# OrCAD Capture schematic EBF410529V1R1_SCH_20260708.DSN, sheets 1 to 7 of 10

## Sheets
1 06 ETH0: size A4; title: 鲁班猫3金手指底板（LubanCat 3_IOF ） RK3576; rev: V0.1; note: ETH0; note: https://yehuosm.tmall.com
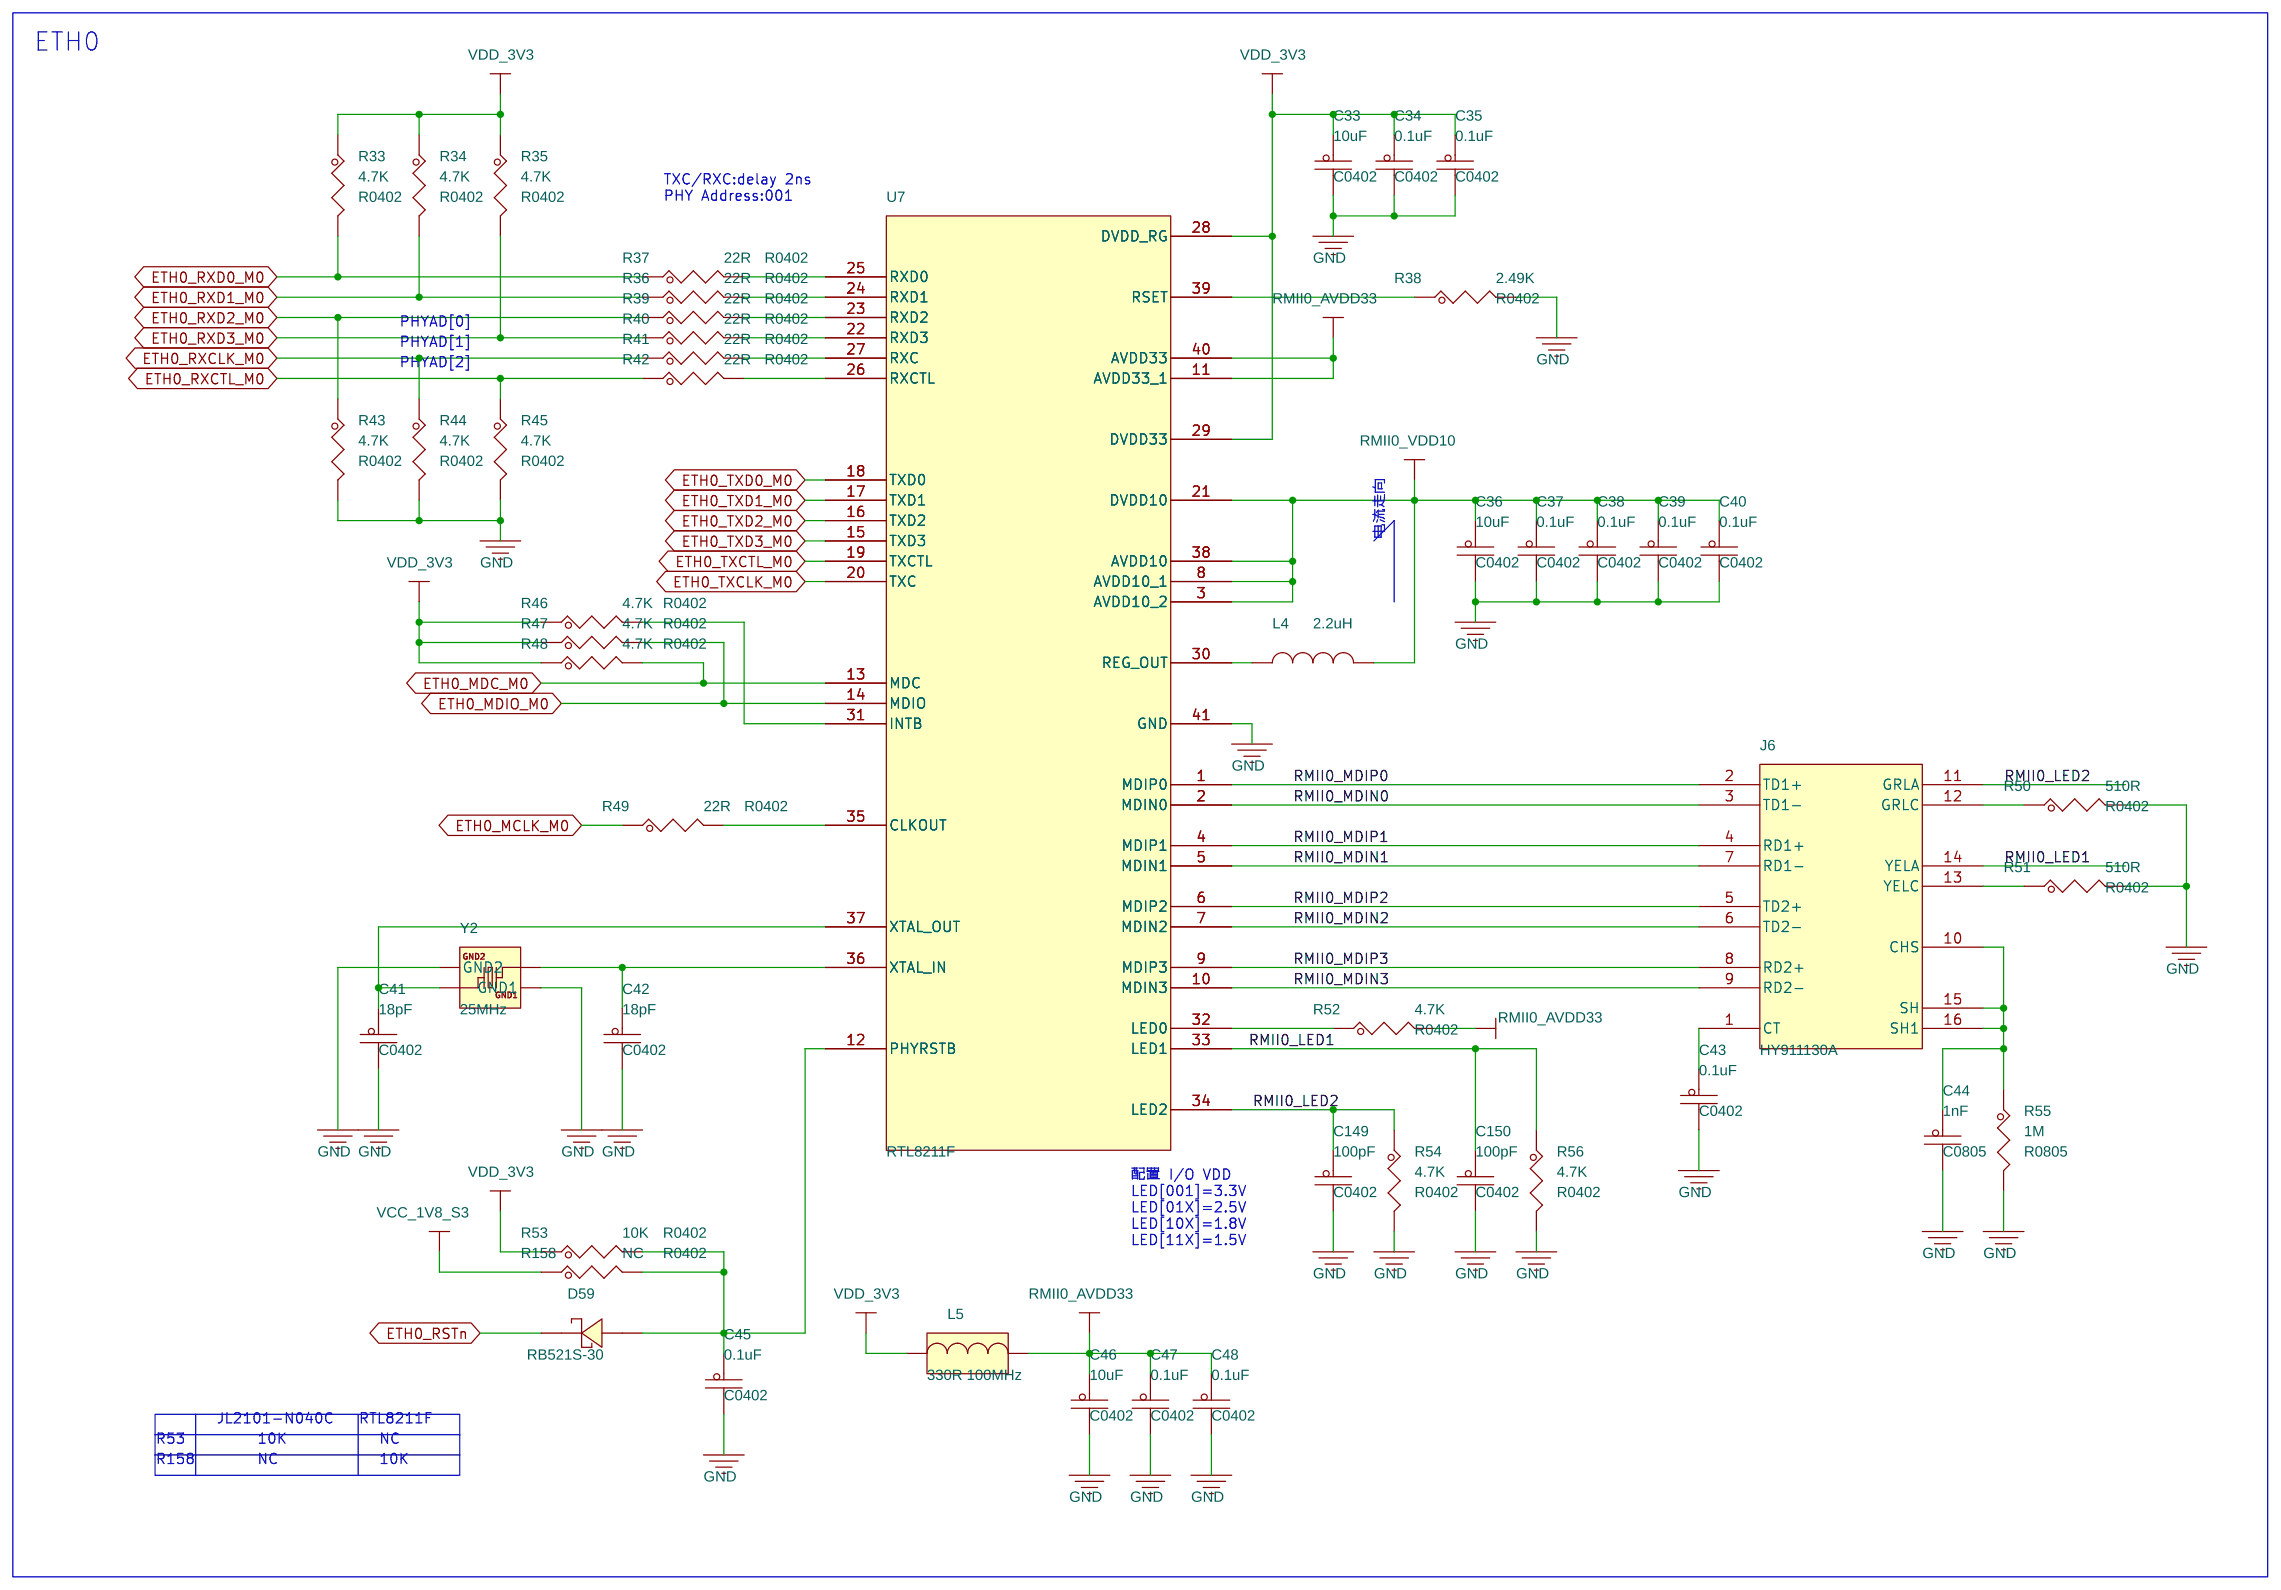
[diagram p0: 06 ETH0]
2 07 ETH1: size A4; note: ETH1
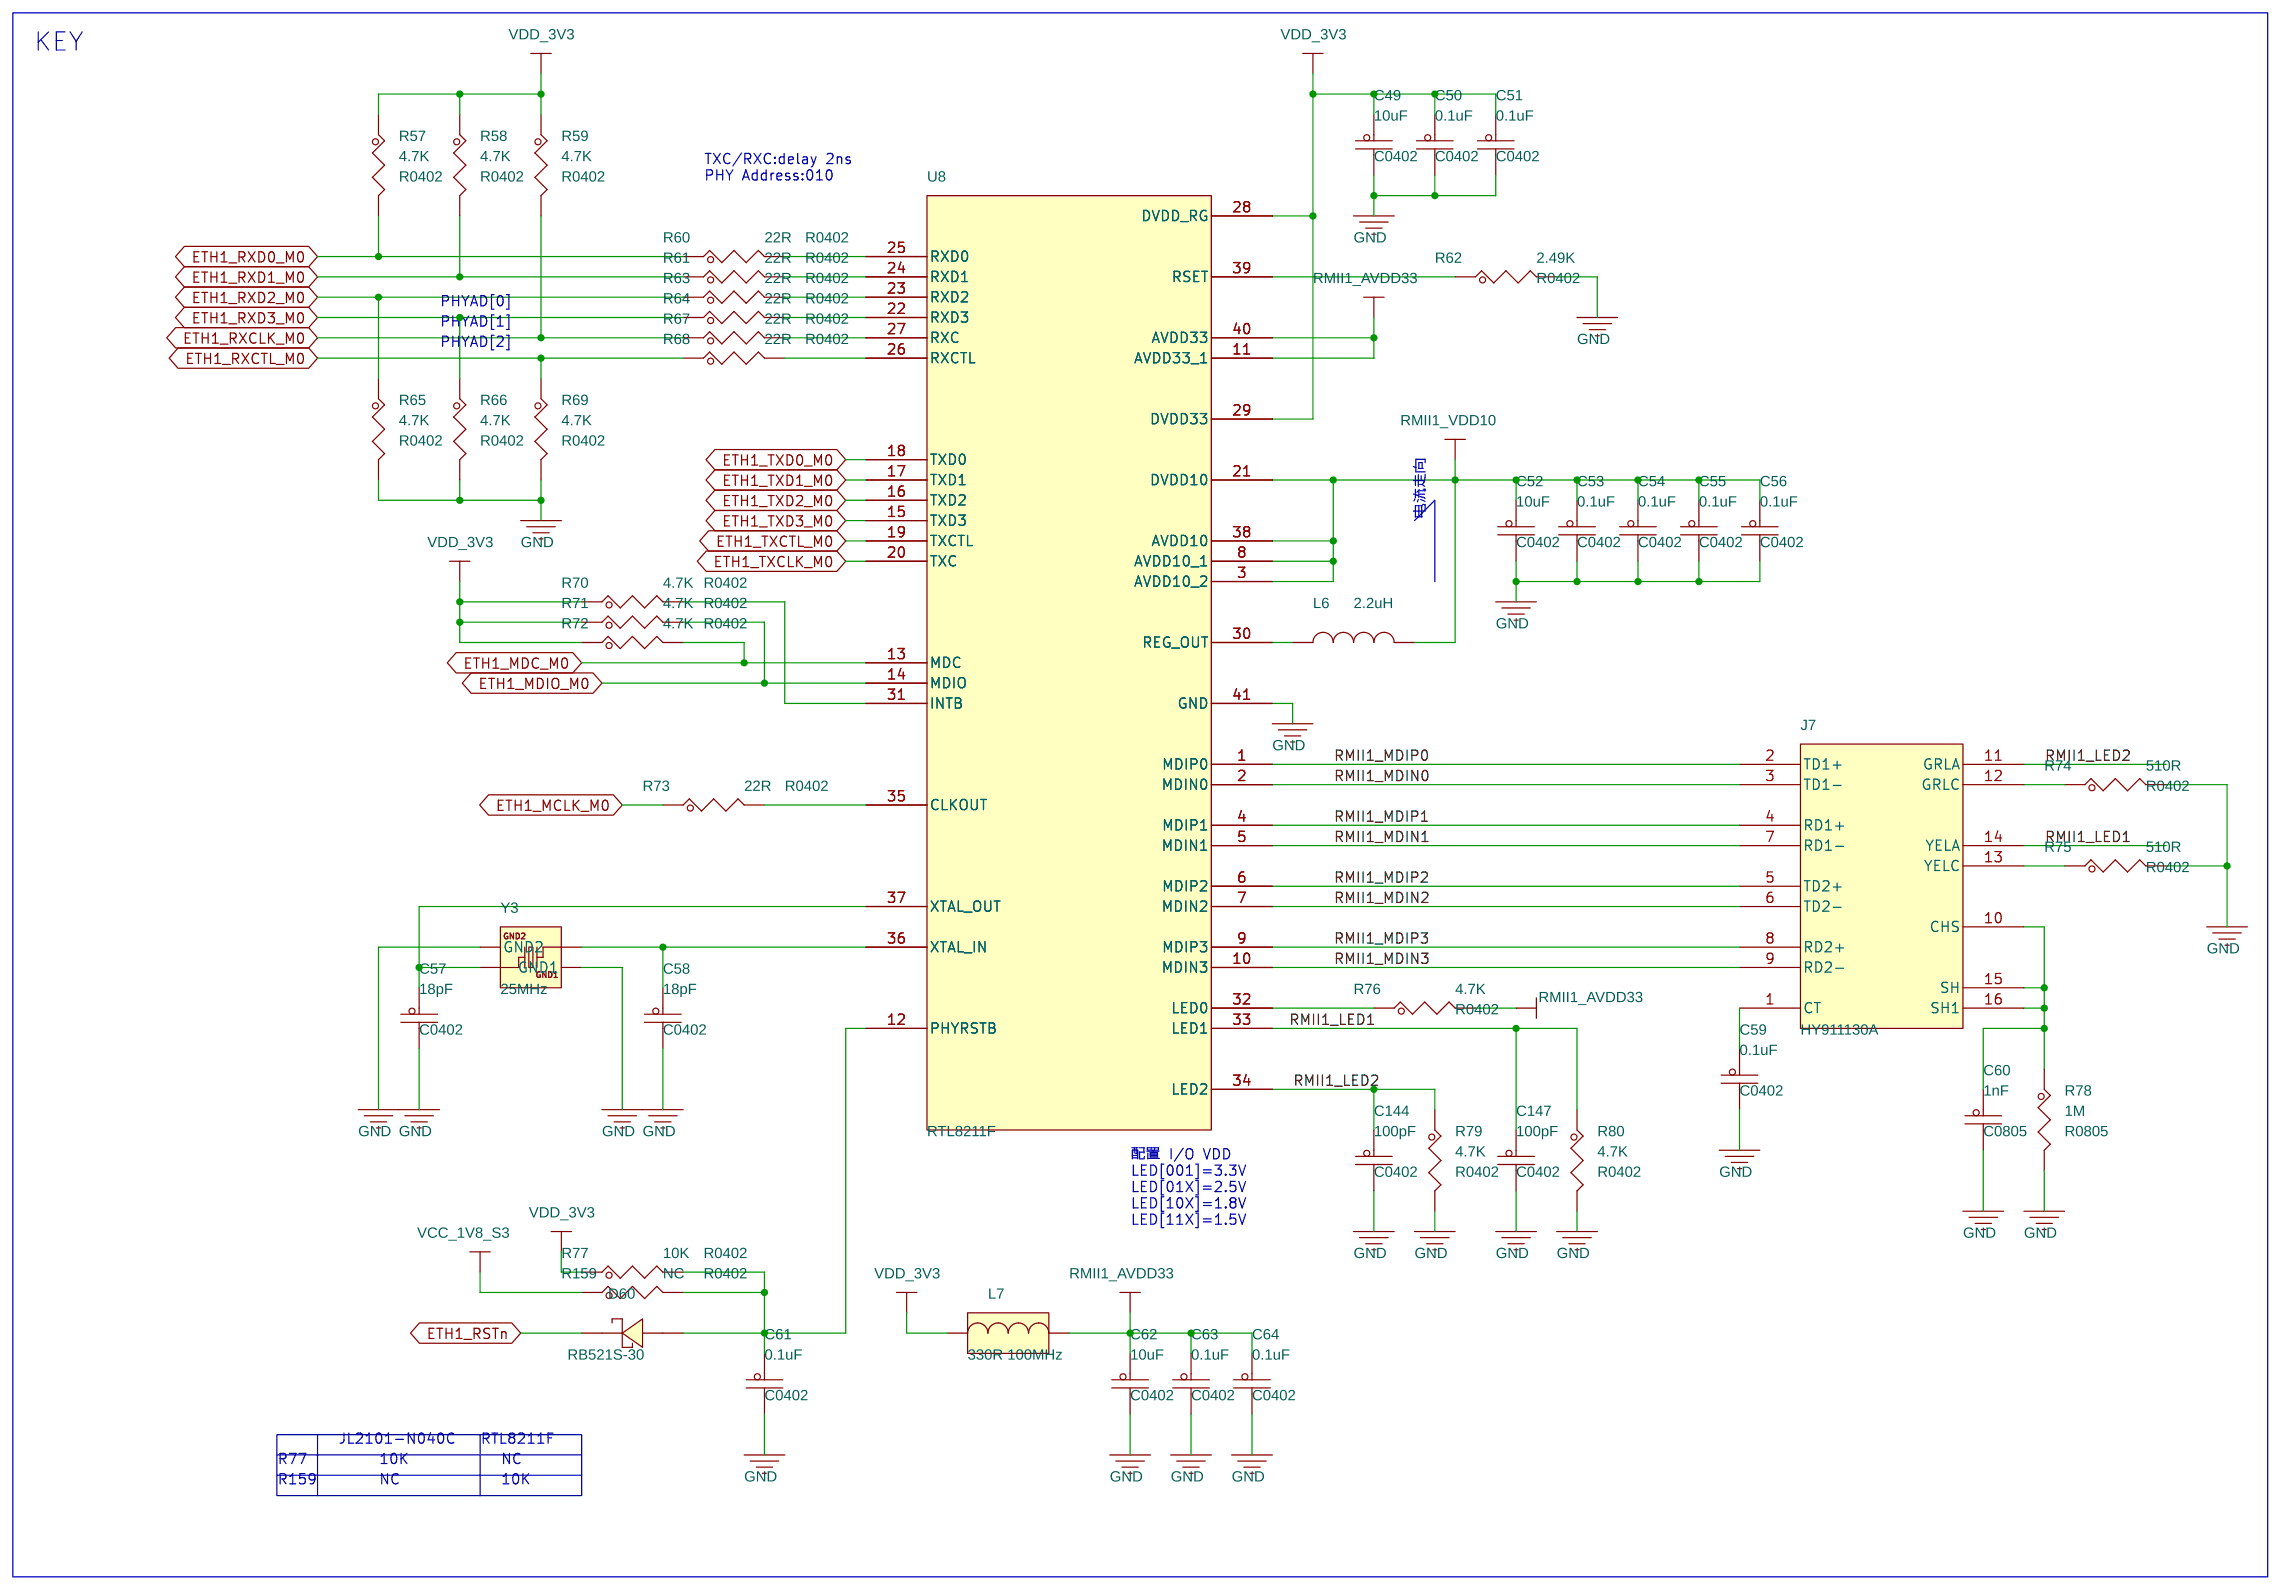
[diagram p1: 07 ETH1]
3 11 MIPI CSI PORT: size A4; note: MIPI CSI PORT
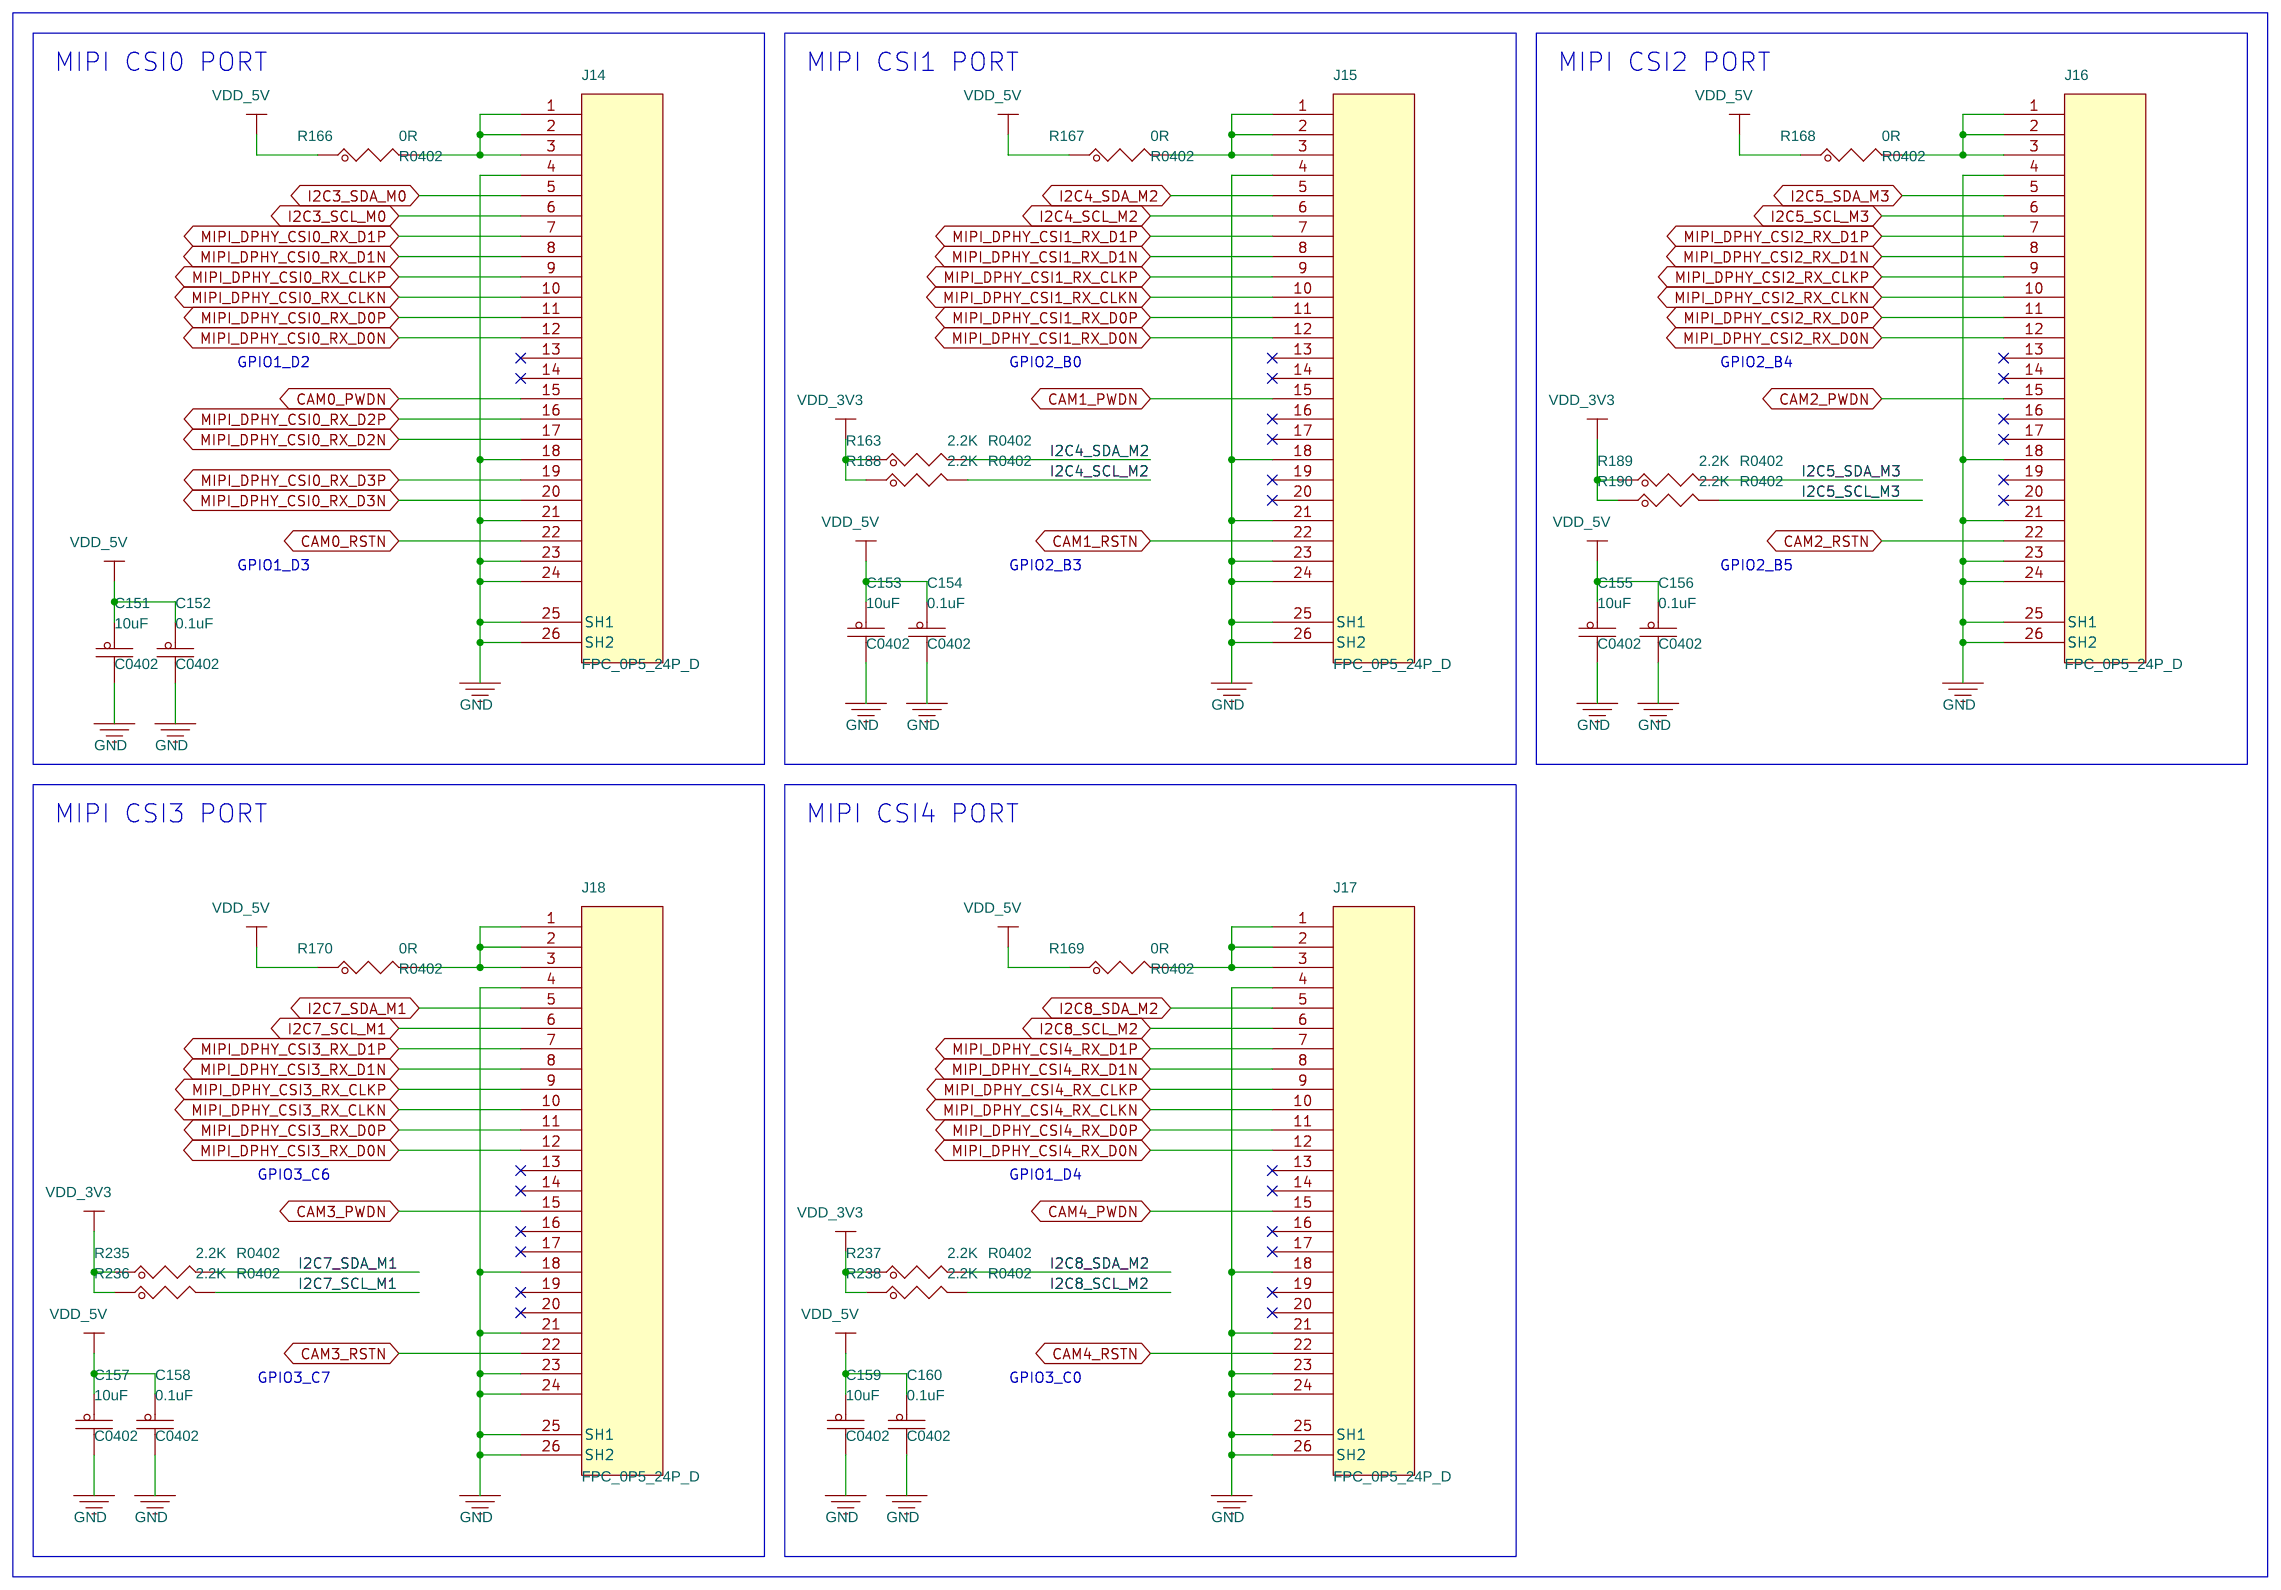
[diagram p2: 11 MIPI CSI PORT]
4 12 MINI PCIE PORT: size A4; note: MINI PCIE PORT
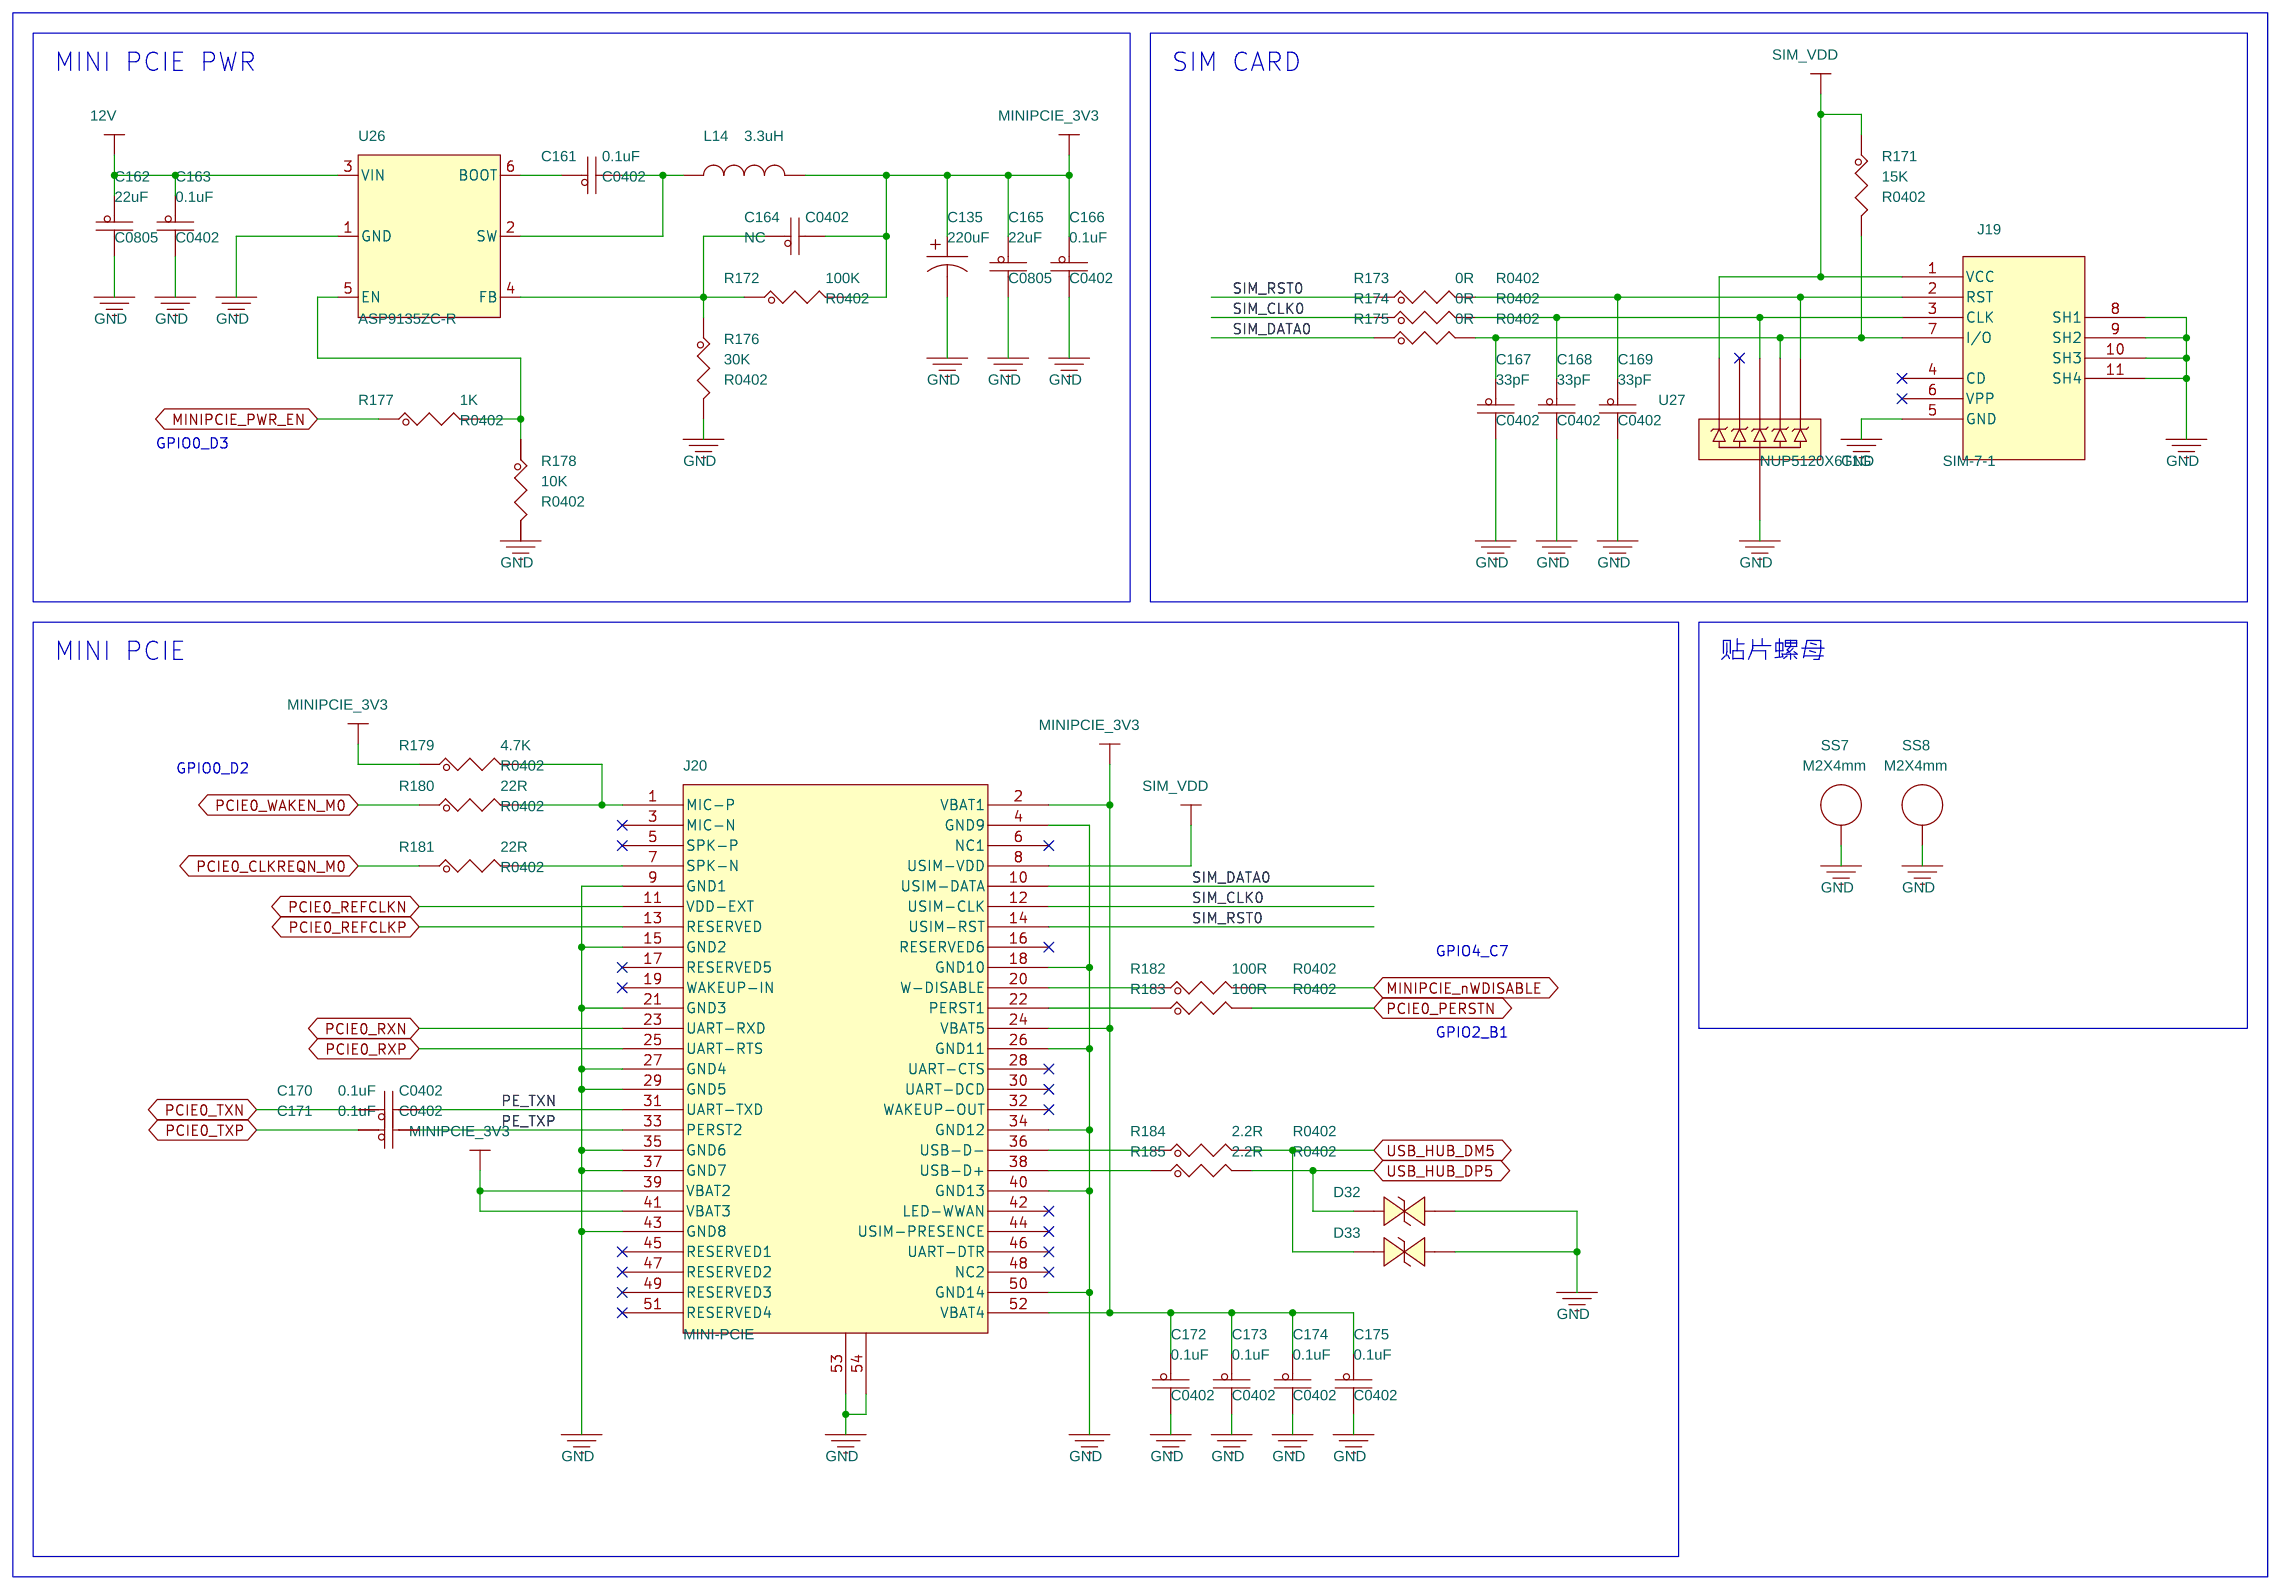
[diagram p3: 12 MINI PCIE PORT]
5 14 POWER OUT PORT: size A4; note: POWER OUT PORT
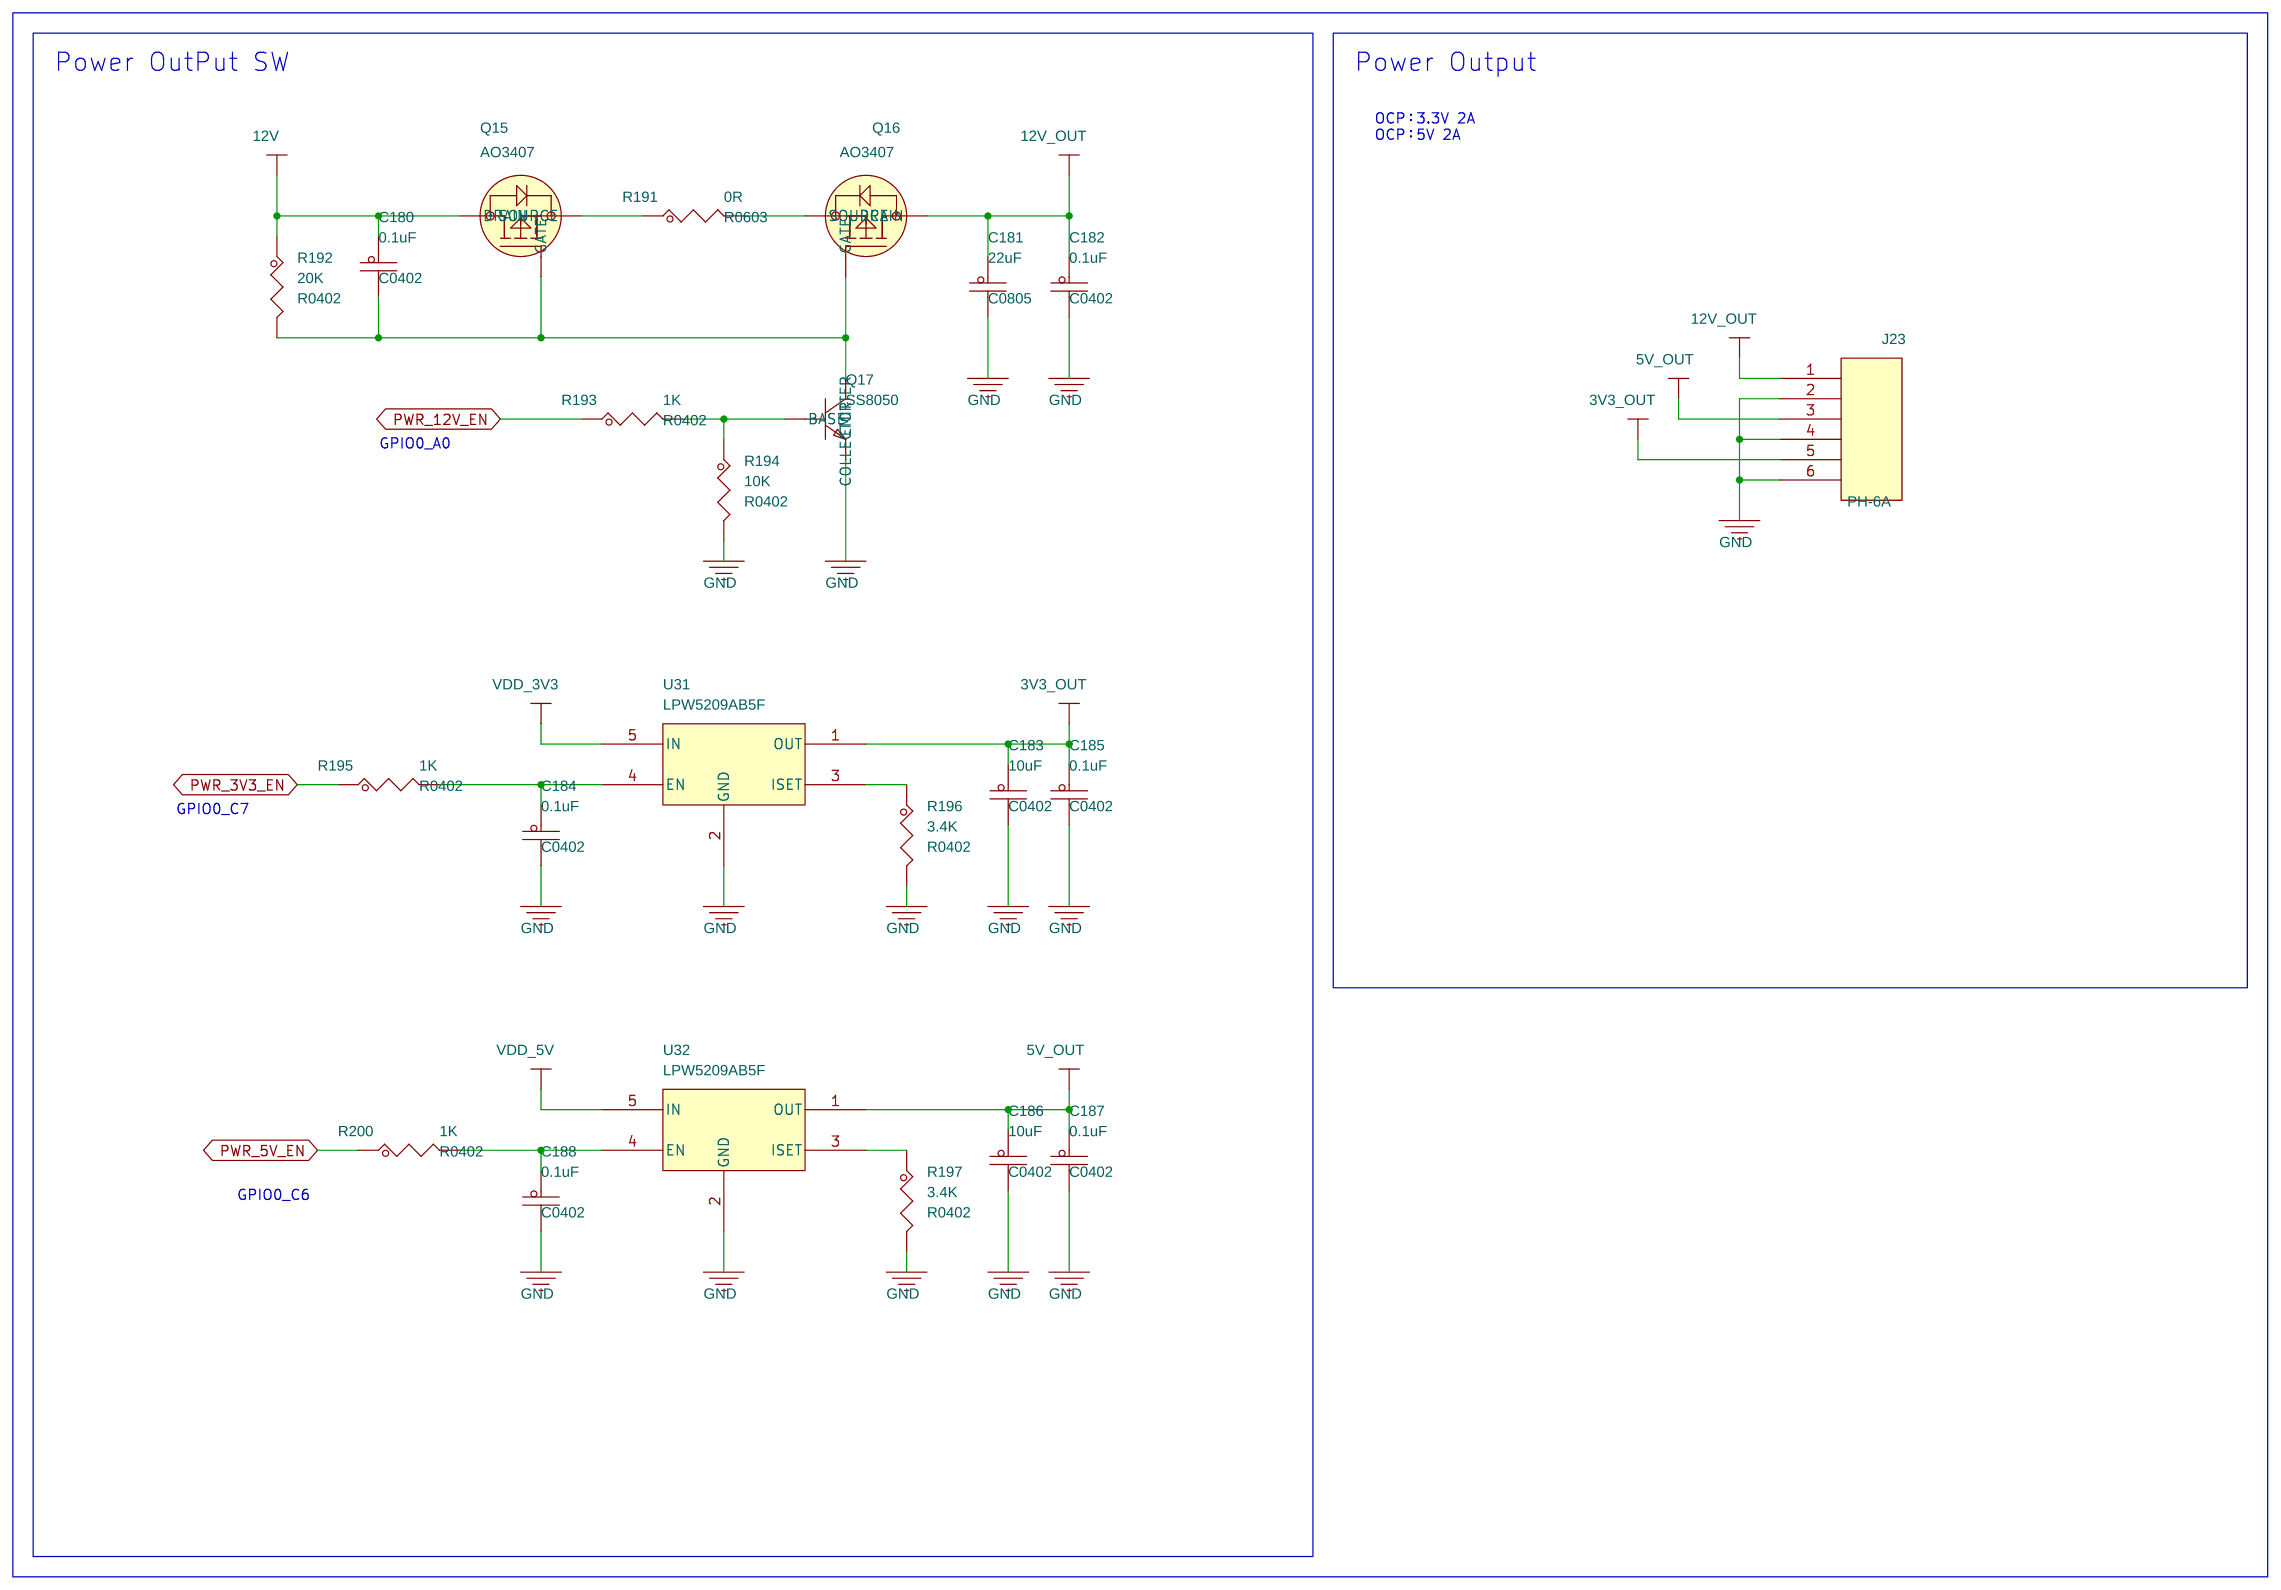
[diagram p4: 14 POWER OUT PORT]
6 08 Audio/WIFI: size A3; note: Audio/WIFI
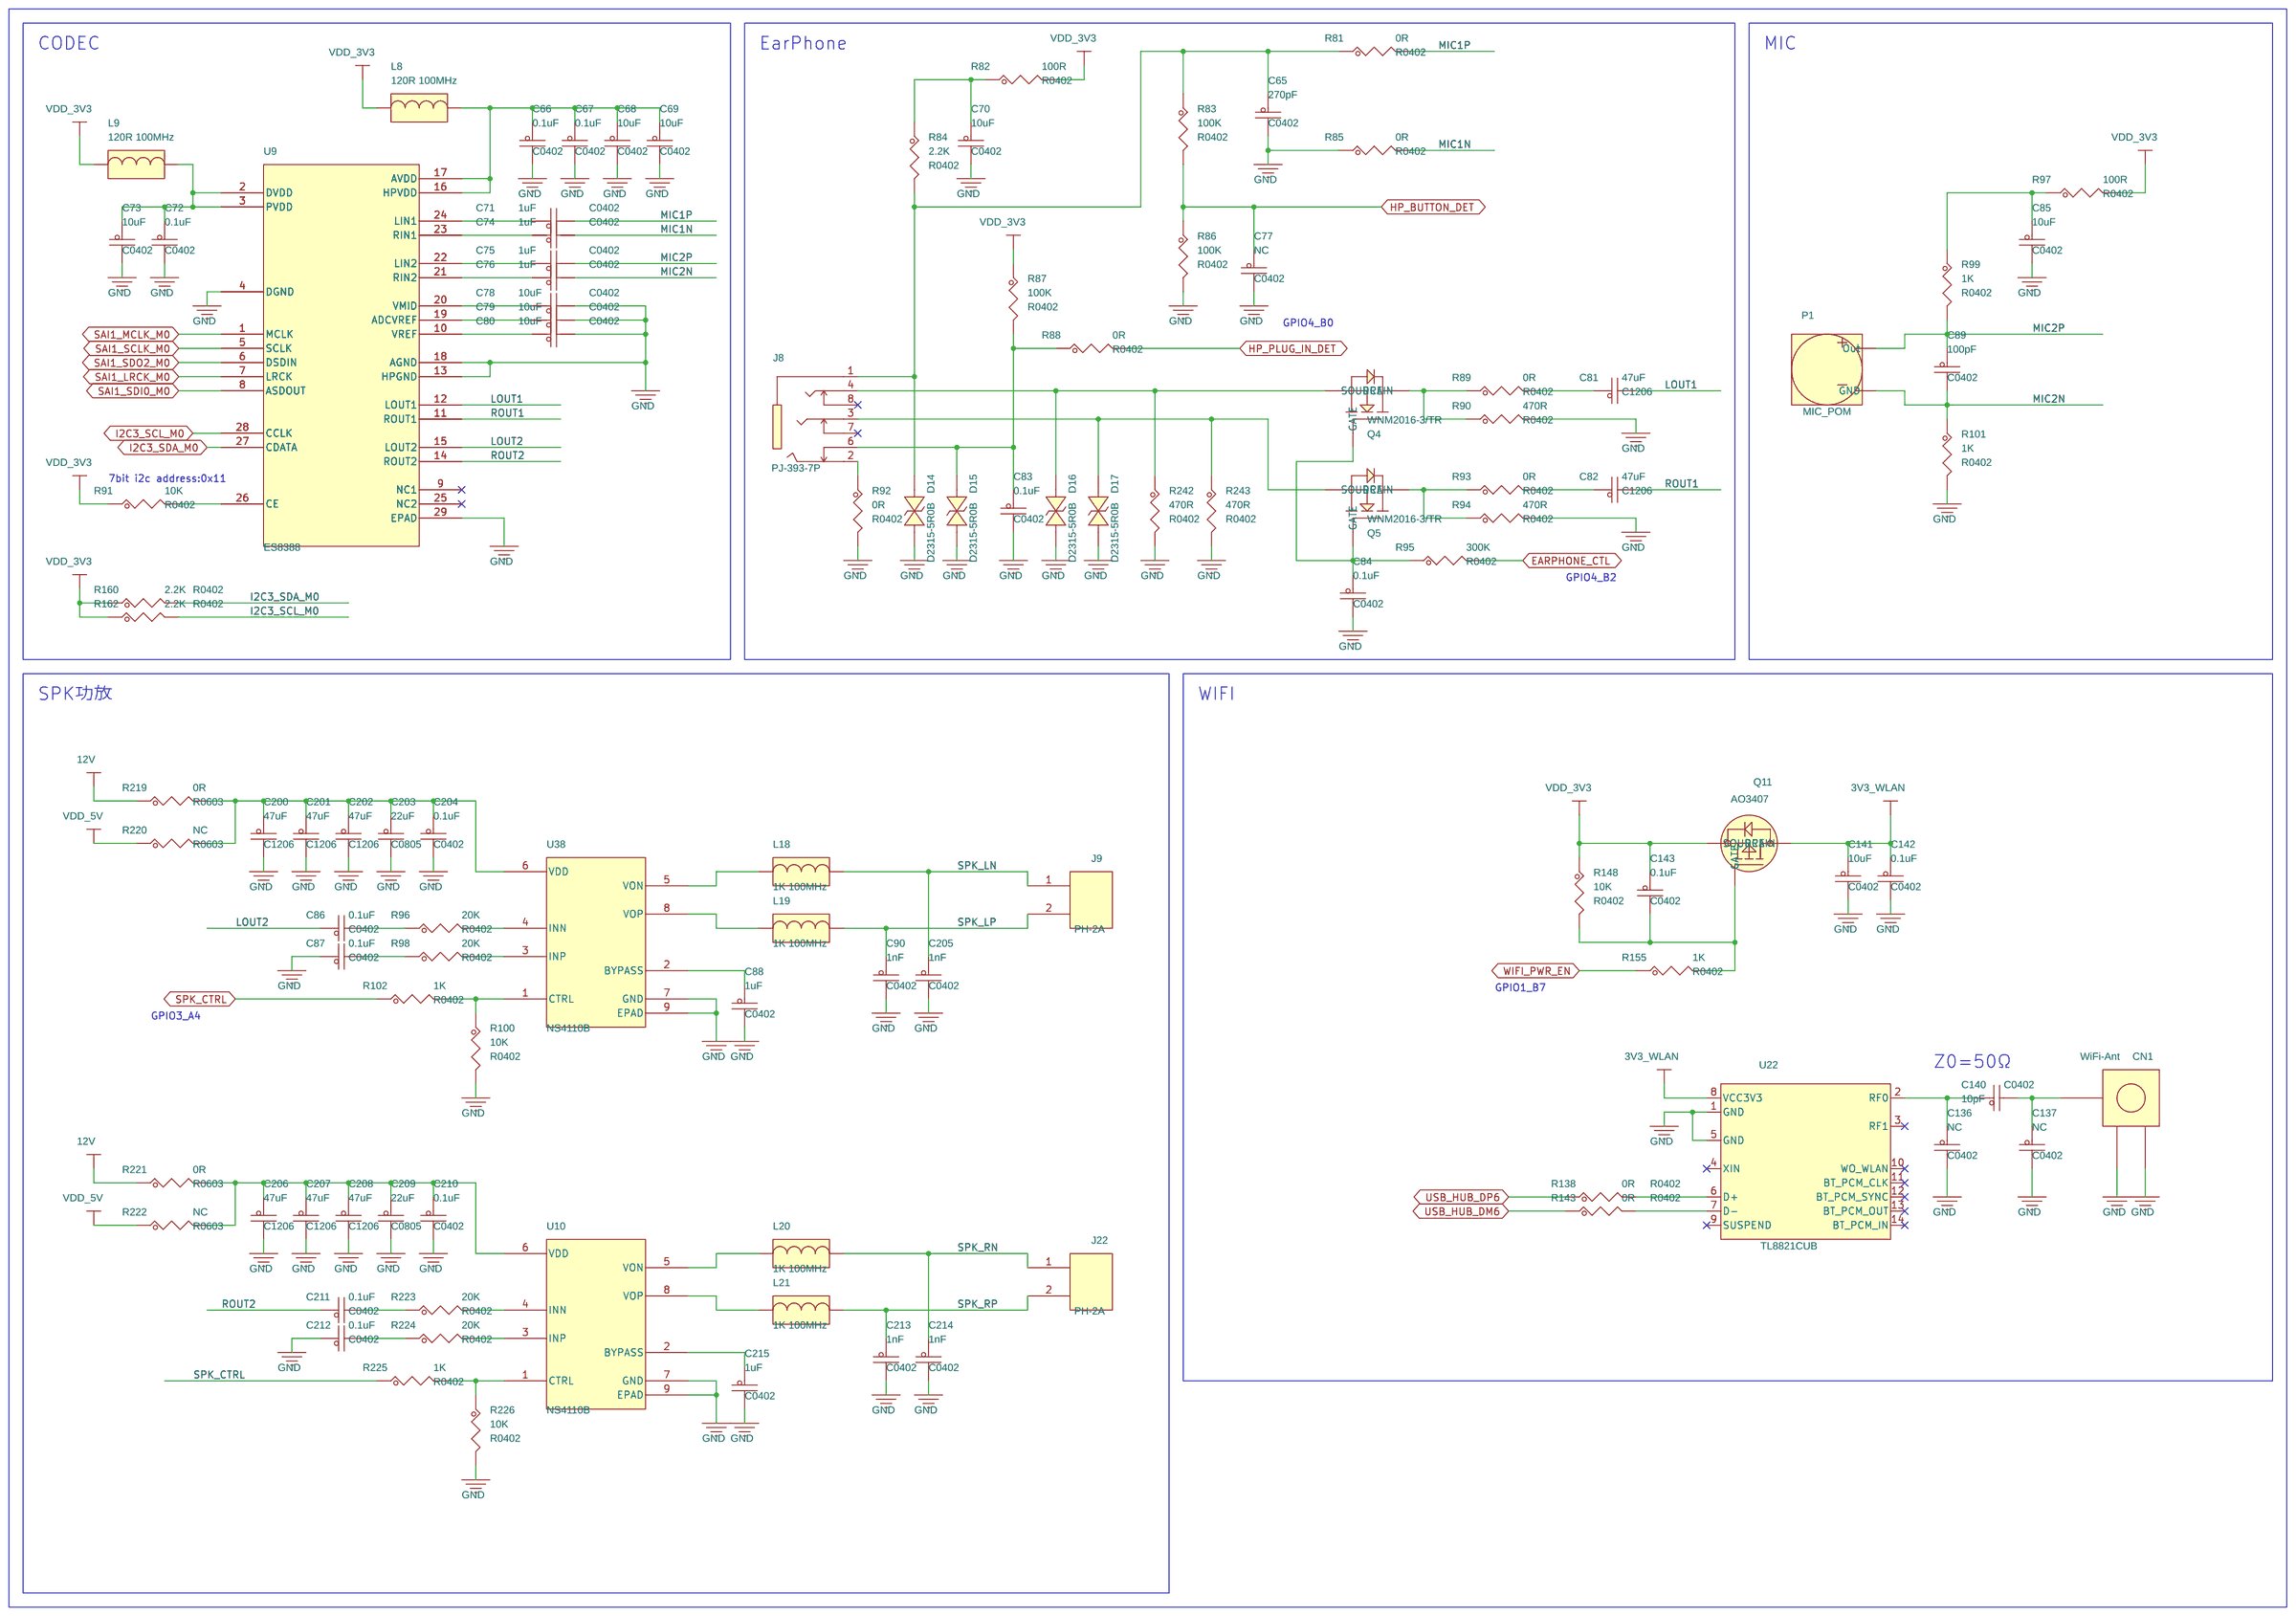
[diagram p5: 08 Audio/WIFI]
7 15 RS232/485/CAN: size A4; note: RS232/485/CAN
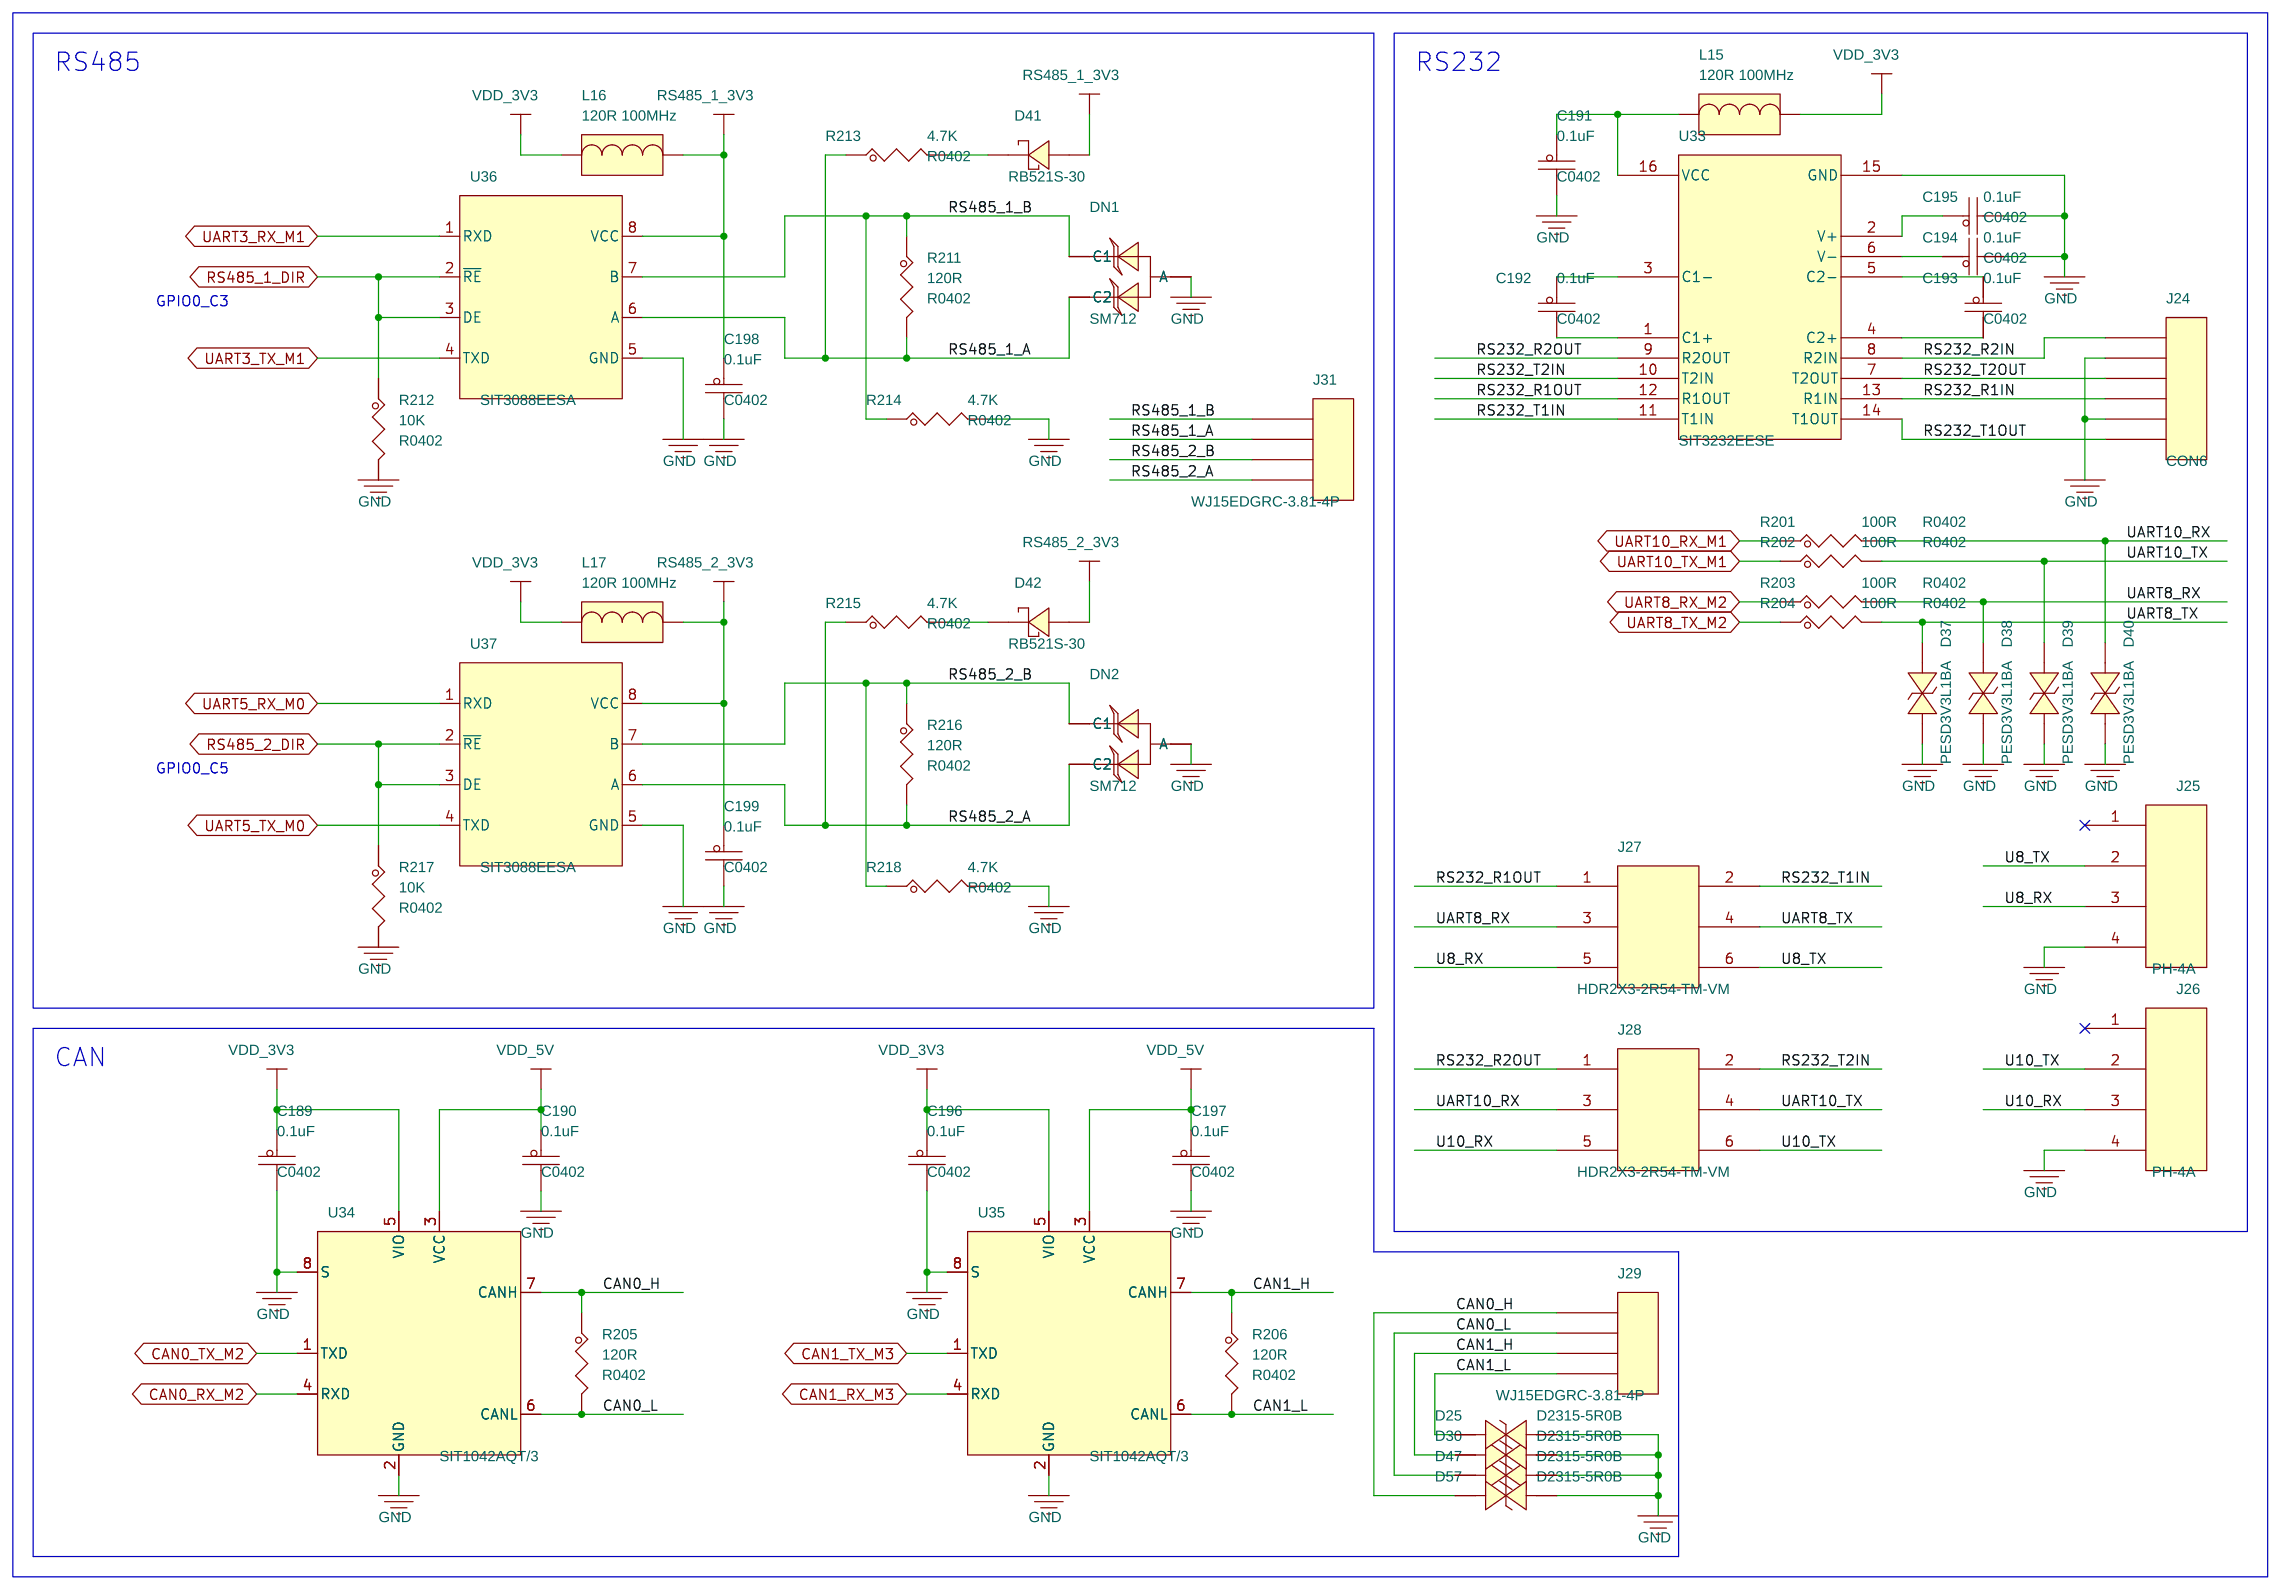
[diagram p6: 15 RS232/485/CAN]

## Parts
sheet 06 ETH0
C33  10uF  [C0402]
C34  0.1uF  [C0402]
C35  0.1uF  [C0402]
C36  10uF  [C0402]
C37  0.1uF  [C0402]
C38  0.1uF  [C0402]
C39  0.1uF  [C0402]
C40  0.1uF  [C0402]
C41  18pF  [C0402]
C42  18pF  [C0402]
C43  0.1uF  [C0402]
C44  1nF  [C0805]
C45  0.1uF  [C0402]
C46  10uF  [C0402]
C47  0.1uF  [C0402]
C48  0.1uF  [C0402]
C149  100pF  [C0402]
C150  100pF  [C0402]
D59  RB521S-30  [SOD523]
J6  HY911130A  [HY911130A]
L4  2.2uH  [L2520]
L5  330R 100MHz  [L0603]
R33  4.7K  [R0402]
R34  4.7K  [R0402]
R35  4.7K  [R0402]
R36  22R  [R0402]
R37  22R  [R0402]
R38  2.49K  [R0402]
R39  22R  [R0402]
R40  22R  [R0402]
R41  22R  [R0402]
R42  22R  [R0402]
R43  4.7K  [R0402]
R44  4.7K  [R0402]
R45  4.7K  [R0402]
R46  4.7K  [R0402]
R47  4.7K  [R0402]
R48  4.7K  [R0402]
R49  22R  [R0402]
R50  510R  [R0402]
R51  510R  [R0402]
R52  4.7K  [R0402]
R53  10K  [R0402]
R54  4.7K  [R0402]
R55  1M  [R0805]
R56  4.7K  [R0402]
R158  NC  [R0402]
U7  RTL8211F  [qfp_40p_r]
Y2  25MHz  [3225]
sheet 07 ETH1
C49  10uF  [C0402]
C50  0.1uF  [C0402]
C51  0.1uF  [C0402]
C52  10uF  [C0402]
C53  0.1uF  [C0402]
C54  0.1uF  [C0402]
C55  0.1uF  [C0402]
C56  0.1uF  [C0402]
C57  18pF  [C0402]
C58  18pF  [C0402]
C59  0.1uF  [C0402]
C60  1nF  [C0805]
C61  0.1uF  [C0402]
C62  10uF  [C0402]
C63  0.1uF  [C0402]
C64  0.1uF  [C0402]
C144  100pF  [C0402]
C147  100pF  [C0402]
D60  RB521S-30  [SOD523]
J7  HY911130A  [HY911130A]
L6  2.2uH  [L2520]
L7  330R 100MHz  [L0603]
R57  4.7K  [R0402]
R58  4.7K  [R0402]
R59  4.7K  [R0402]
R60  22R  [R0402]
R61  22R  [R0402]
R62  2.49K  [R0402]
R63  22R  [R0402]
R64  22R  [R0402]
R65  4.7K  [R0402]
R66  4.7K  [R0402]
R67  22R  [R0402]
R68  22R  [R0402]
R69  4.7K  [R0402]
R70  4.7K  [R0402]
R71  4.7K  [R0402]
R72  4.7K  [R0402]
R73  22R  [R0402]
R74  510R  [R0402]
R75  510R  [R0402]
R76  4.7K  [R0402]
R77  10K  [R0402]
R78  1M  [R0805]
R79  4.7K  [R0402]
R80  4.7K  [R0402]
R159  NC  [R0402]
U8  RTL8211F  [qfp_40p_r]
Y3  25MHz  [3225]
sheet 08 Audio/WIFI
C65  270pF  [C0402]
C66  0.1uF  [C0402]
C67  0.1uF  [C0402]
C68  10uF  [C0402]
C69  10uF  [C0402]
C70  10uF  [C0402]
C71  1uF  [C0402]
C72  0.1uF  [C0402]
C73  10uF  [C0402]
C74  1uF  [C0402]
C75  1uF  [C0402]
C76  1uF  [C0402]
C77  NC  [C0402]
C78  10uF  [C0402]
C79  10uF  [C0402]
C80  10uF  [C0402]
C81  47uF  [C1206]
C82  47uF  [C1206]
C83  0.1uF  [C0402]
C84  0.1uF  [C0402]
C85  10uF  [C0402]
C86  0.1uF  [C0402]
C87  0.1uF  [C0402]
C88  1uF  [C0402]
C89  100pF  [C0402]
C90  1nF  [C0402]
C136  NC  [C0402]
C137  NC  [C0402]
C140  10pF  [C0402]
C141  10uF  [C0402]
C142  0.1uF  [C0402]
C143  0.1uF  [C0402]
C200  47uF  [C1206]
C201  47uF  [C1206]
C202  47uF  [C1206]
C203  22uF  [C0805]
C204  0.1uF  [C0402]
C205  1nF  [C0402]
C206  47uF  [C1206]
C207  47uF  [C1206]
C208  47uF  [C1206]
C209  22uF  [C0805]
C210  0.1uF  [C0402]
C211  0.1uF  [C0402]
C212  0.1uF  [C0402]
C213  1nF  [C0402]
C214  1nF  [C0402]
C215  1uF  [C0402]
CN1  WiFi-Ant  [UFL-3]
D14  D2315-5R0B  [esd0402]
D15  D2315-5R0B  [esd0402]
D16  D2315-5R0B  [esd0402]
D17  D2315-5R0B  [esd0402]
J8  PJ-393-7P  [AV7_6x14r50_TM]
J9  PH-2A  [PH-1x2-2P0_l]
J22  PH-2A  [PH-1x2-2P0_l]
L8  120R 100MHz  [L0402]
L9  120R 100MHz  [L0402]
L18  1K 100MHz  [L0603]
L19  1K 100MHz  [L0603]
L20  1K 100MHz  [L0603]
L21  1K 100MHz  [L0603]
P1  MIC_POM  [MIC2-4R00-TM]
Q4  WNM2016-3/TR  [SOT23]
Q5  WNM2016-3/TR  [SOT23]
Q11  AO3407  [SOT23]
R81  0R  [R0402]
R82  100R  [R0402]
R83  100K  [R0402]
R84  2.2K  [R0402]
R85  0R  [R0402]
R86  100K  [R0402]
R87  100K  [R0402]
R88  0R  [R0402]
R89  0R  [R0402]
R90  470R  [R0402]
R91  10K  [R0402]
R92  0R  [R0402]
R93  0R  [R0402]
R94  470R  [R0402]
R95  300K  [R0402]
R96  20K  [R0402]
R97  100R  [R0402]
R98  20K  [R0402]
R99  1K  [R0402]
R100  10K  [R0402]
R101  1K  [R0402]
R102  1K  [R0402]
R138  0R  [R0402]
R143  0R  [R0402]
R148  10K  [R0402]
R155  1K  [R0402]
R160  2.2K  [R0402]
R162  2.2K  [R0402]
R219  0R  [R0603]
R220  NC  [R0603]
R221  0R  [R0603]
R222  NC  [R0603]
R223  20K  [R0402]
R224  20K  [R0402]
R225  1K  [R0402]
R226  10K  [R0402]
R242  470R  [R0402]
R243  470R  [R0402]
U9  ES8388  [qfn28_0r45-4x4EP2R6X2R6]
U10  NS4110B  [SOP-8-EP-2R5X3R4]
U22  TL8821CUB  [RL-UM02WBS-8723BU]
U38  NS4110B  [SOP-8-EP-2R5X3R4]
sheet 11 MIPI CSI PORT
C151  10uF  [C0402]
C152  0.1uF  [C0402]
C153  10uF  [C0402]
C154  0.1uF  [C0402]
C155  10uF  [C0402]
C156  0.1uF  [C0402]
C157  10uF  [C0402]
C158  0.1uF  [C0402]
C159  10uF  [C0402]
C160  0.1uF  [C0402]
J14  FPC_0P5_24P_D  [fpc_24p_0p5]
J15  FPC_0P5_24P_D  [fpc_24p_0p5]
J16  FPC_0P5_24P_D  [fpc_24p_0p5]
J17  FPC_0P5_24P_D  [fpc_24p_0p5]
J18  FPC_0P5_24P_D  [fpc_24p_0p5]
R163  2.2K  [R0402]
R166  0R  [R0402]
R167  0R  [R0402]
R168  0R  [R0402]
R169  0R  [R0402]
R170  0R  [R0402]
R188  2.2K  [R0402]
R189  2.2K  [R0402]
R190  2.2K  [R0402]
R235  2.2K  [R0402]
R236  2.2K  [R0402]
R237  2.2K  [R0402]
R238  2.2K  [R0402]
sheet 12 MINI PCIE PORT
C135  220uF  [CASE-B_3528]
C161  0.1uF  [C0402]
C162  22uF  [C0805]
C163  0.1uF  [C0402]
C164  NC  [C0402]
C165  22uF  [C0805]
C166  0.1uF  [C0402]
C167  33pF  [C0402]
C168  33pF  [C0402]
C169  33pF  [C0402]
C170  0.1uF  [C0402]
C171  0.1uF  [C0402]
C172  0.1uF  [C0402]
C173  0.1uF  [C0402]
C174  0.1uF  [C0402]
C175  0.1uF  [C0402]
D32  KLXES15AAA1  [ES0402]
D33  KLXES15AAA1  [ES0402]
J19  SIM-7-1  [nano_sim]
J20  MINI-PCIE  [pcie_52p]
L14  3.3uH  [l4520]
R171  15K  [R0402]
R172  100K  [R0402]
R173  0R  [R0402]
R174  0R  [R0402]
R175  0R  [R0402]
R176  30K  [R0402]
R177  1K  [R0402]
R178  10K  [R0402]
R179  4.7K  [R0402]
R180  22R  [R0402]
R181  22R  [R0402]
R182  100R  [R0402]
R183  100R  [R0402]
R184  2.2R  [R0402]
R185  2.2R  [R0402]
SS7  M2X4mm  [SMTWE_M2]
SS8  M2X4mm  [SMTWE_M2]
U26  ASP9135ZC-R  [SOT23_6]
U27  NUP5120X6T1G  [SOT563]
sheet 14 POWER OUT PORT
C180  0.1uF  [C0402]
C181  22uF  [C0805]
C182  0.1uF  [C0402]
C183  10uF  [C0402]
C184  0.1uF  [C0402]
C185  0.1uF  [C0402]
C186  10uF  [C0402]
C187  0.1uF  [C0402]
C188  0.1uF  [C0402]
J23  PH-6A  [PH-1X6-2P0]
Q15  AO3407  [SOT23]
Q16  AO3407  [SOT23]
Q17  SS8050  [SOT23]
R191  0R  [R0603]
R192  20K  [R0402]
R193  1K  [R0402]
R194  10K  [R0402]
R195  1K  [R0402]
R196  3.4K  [R0402]
R197  3.4K  [R0402]
R200  1K  [R0402]
U31  LPW5209AB5F  [SOT23-5]
U32  LPW5209AB5F  [SOT23-5]
sheet 15 RS232/485/CAN
C189  0.1uF  [C0402]
C190  0.1uF  [C0402]
C191  0.1uF  [C0402]
C192  0.1uF  [C0402]
C193  0.1uF  [C0402]
C194  0.1uF  [C0402]
C195  0.1uF  [C0402]
C196  0.1uF  [C0402]
C197  0.1uF  [C0402]
C198  0.1uF  [C0402]
C199  0.1uF  [C0402]
D25  D2315-5R0B  [esd0402]
D30  D2315-5R0B  [esd0402]
D37  PESD3V3L1BA  [sod323_t]
D38  PESD3V3L1BA  [sod323_t]
D39  PESD3V3L1BA  [sod323_t]
D40  PESD3V3L1BA  [sod323_t]
D41  RB521S-30  [SOD523]
D42  RB521S-30  [SOD523]
D47  D2315-5R0B  [esd0402]
D57  D2315-5R0B  [esd0402]
DN1  SM712  [SOT23]
DN2  SM712  [SOT23]
J24  CON6  [DB2ERC-3P81-6P]
J25  PH-4A  [PH-1X4-2P0]
J26  PH-4A  [PH-1X4-2P0]
J27  HDR2X3-2R54-TM-VM  [HDR2X3-2R54-TM-VM]
J28  HDR2X3-2R54-TM-VM  [HDR2X3-2R54-TM-VM]
J29  WJ15EDGRC-3.81-4P  [DB2ERC-3P81-4P]
J31  WJ15EDGRC-3.81-4P  [DB2ERC-3P81-4P]
L15  120R 100MHz  [L0402]
L16  120R 100MHz  [L0402]
L17  120R 100MHz  [L0402]
R201  100R  [R0402]
R202  100R  [R0402]
R203  100R  [R0402]
R204  100R  [R0402]
R205  120R  [R0402]
R206  120R  [R0402]
R211  120R  [R0402]
R212  10K  [R0402]
R213  4.7K  [R0402]
R214  4.7K  [R0402]
R215  4.7K  [R0402]
R216  120R  [R0402]
R217  10K  [R0402]
R218  4.7K  [R0402]
U33  SIT3232EESE  [SOIC16]
U34  SIT1042AQT/3  [SOP8]
U35  SIT1042AQT/3  [SOP8]
U36  SIT3088EESA  [SOP8]
U37  SIT3088EESA  [SOP8]

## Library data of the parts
C33 C36 C46 C49 C52 C62 C68-C70 C73 C78-C80 C85 C141 C151 C153 C155 C157 C159 C183 C186 = CAP_NP: voltage: 10V; 规格: 贴片电容10uF 20% 10V X5R 0402; 规格编号: CL05A106MP8NUB8; 规格书: 三星电容.pdf; 价格: 0.518415; 类别: 贴片电容0402; 品牌: 三星; 生命周期: 量产; 条码: EBF29060247
C34 C35 C37-C40 C43 C45 C47 C48 C50 C51 C53-C56 C59 C61 C63 C64 C66 C67 C72 C83 C84 C86 C87 C142 C143 C152 C154 C156 C158 C160 C161 C163 C166 C170-C175 C180 C182 C184 C185 C187-C199 C204 C210-C212 = CAP_NP: voltage: 50V; 规格: 贴片电容0.1uF 10% 50V X5R 0402; 规格编号: 0402X104K500NT; 规格书: 风华电容.pdf; 价格: 0.029826; 类别: 贴片电容0402; 品牌: 风华; 生命周期: 量产; 条码: EBF29060118
C41 C42 C57 C58 = CAP_NP: voltage: 50V; 规格: 贴片电容18pF 5% 50V C0G 0402; 规格编号: 0402CG180J500NT; 规格书: 风华电容.pdf; 价格: 0.00515; 类别: 贴片电容0402; 品牌: 风华; 生命周期: 量产; 条码: EBF29060235
C44 C60 = CAP_NP: voltage: 1kv; 规格: 贴片电容1nF 10% 1kV X7R 0805; 规格编号: 0805B102K102CT; 规格书: 华新科0805系列高压贴片电容.pdf; 价格: 0.083527; 类别: 贴片电容0805; 品牌: 华新科; 生命周期: 量产; 条码: EBF29060304
C89 C144 C147 C149 C150 = CAP_NP: voltage: 50V; 规格: 贴片电容100pF 5% 50V C0G 0402; 规格编号: GRT1555C1H101JA; 规格书: 村田040系列贴片电容.pdf; 价格: 0.034837; 类别: 贴片电容0402; 品牌: 村田; 生命周期: 量产; 条码: EBF29060302
D41 D42 D59 D60 = DIODE_SCHTKY: 规格: 直流反向耐压(Vr)：30V 平均整流电流(Io)：200mA 正向压降(Vf)：500mV@200mA 30V@100mA,VF=350mV@10mA; 规格书: 江苏长电_RB521S-30.pdf; 价格: 0.06781; 类别: 贴片肖特基二极管; 品牌: 江苏长电; 生命周期: 量产; 条码: EBFCIS221114153437
J6 J7 = HY911130A: 规格: 屏蔽式以太网连接器RJ45 引脚数14 LED灯黄绿 1000M; 规格书: 汉仁_1000M_ HY911130A.pdf; 价格: 11.12; 可替代料: EBF29040053; 类别: 网口; 品牌: 汉仁; 生命周期: 量产; 条码: EBF29040053
L4 L6 = IND: 规格: 功率电感2.2uH 2.2uH ±20% 2.06A 85mΩ; 规格编号: WIP252012P-2R2ML; 规格书: 佳邦_ WIP252012P-2R2ML.pdf; 价格: 0.129914; 类别: 贴片电感2520; 品牌: 佳邦; 生命周期: 量产; 条码: EBFCIS220927171910
L5 L7 = BEAD: 规格: 磁珠330Ω @100MHz 额定电流1.7A 直流电阻80mΩ; 规格编号: MPZ1608S331ATA00; 规格书: TDK-MPZ1608S331ATA00.pdf; 类别: 贴片磁珠0603; 品牌: TDK; 生命周期: 量产; 条码: EBF29050003
R33-R35 R43-R48 R52 R54 R56-R59 R65 R66 R69-R72 R76 R79 R80 R179 R213-R215 R218 = RES: 规格: 贴片电阻4.7K 1% 1/16W 0402; 规格编号: RI0402L4701FT; 规格书: 合科泰-RI系列电阻.pdf; 类别: 贴片电阻0402; 品牌: 合科泰; 生命周期: 量产; 条码: EBF29070047
R36 R37 R39-R42 R49 R60 R61 R63 R64 R67 R68 R73 R180 R181 = RES: 规格: 贴片电阻22R 1% 1/16W 0402; 规格编号: RI0402L22R0FT; 规格书: 合科泰-RI系列电阻.pdf; 类别: 贴片电阻0402; 品牌: 合科泰; 生命周期: 量产; 条码: EBF29070181
R38 R62 = RES: 规格: 贴片电阻2.49K 1% 1/16W 0402; 规格编号: 0402WGF2491TCE; 规格书: 厚声-无铅厚膜电阻.pdf; 价格: 0.004709; 类别: 贴片电阻0402; 品牌: 厚声; 生命周期: 量产; 条码: EBF29070292
R50 R51 R74 R75 = RES: 规格: 贴片电阻510R 1% 1/16W 0402; 规格编号: 0402WGF5100TCE; 规格书: 厚声-无铅厚膜电阻.pdf; 价格: 0.003791; 类别: 贴片电阻0402; 品牌: 厚声; 生命周期: 量产; 条码: EBF29070293
R53 R77 R91 R100 R148 R178 R194 R212 R217 R226 = RES: 规格: 贴片电阻10K 1% 1/16W 0402; 规格编号: 0402WGF1002TCE; 规格书: 厚声-无铅厚膜电阻.pdf; 价格: 0.002773; 类别: 贴片电阻0402; 品牌: 厚声; 生命周期: 量产; 条码: EBF29070046
R55 R78 = RES: 规格: 贴片电阻1M 1% 1/8W 0805; 规格编号: AC0805FR-071ML; 规格书: YAGEO国巨厚膜无铅电阻.pdf; 价格: 0.02396; 类别: 贴片电阻0805; 品牌: 国巨; 生命周期: 量产; 条码: EBF29070294
R158 R159 = RES: 规格: 贴片电阻NC 预留; 类别: 贴片电阻0402; 条码: EBF29070087
U7 U8 = RTL8211F: 规格: 以太网芯片 10M/100M/1000M 控制接口：RGMII RGMII电压：3.3V/2.5V/1.8V/1.5V; 规格编号: RTL8211F-CG; 规格书: 瑞昱_RTL8211F-CG.pdf; 价格: 15.2; 类别: 以太网芯片; 品牌: 瑞昱; 生命周期: 量产; 条码: EBF29150018
Y2 Y3 = CRYSTAL_4P: 规格: 无源晶振25MHz ±10ppm 50Ω 16pF -40℃~+85℃ 3225; 规格编号: X322525MQB4SI; 规格书: 扬兴科技-25MHZ.pdf; 价格: 0.385846; 类别: 贴片晶振 3225; 品牌: 扬兴科技; 生命周期: 量产; 条码: EBF29100005
C65 = CAP_NP: voltage: 50V; 规格: 贴片电容270pF 5% 50V C0G 0402; 规格编号: 0402CG271J500NT; 规格书: 风华电容.pdf; 价格: 0.018204; 类别: 贴片电容0402; 品牌: 风华; 生命周期: 量产; 条码: EBF29060290
C71 C74-C76 C88 C215 = CAP_NP: voltage: 10V; 规格: 贴片电容1uF 10% 10V X5R 0402; 规格编号: 0402X105K100NT; 规格书: 风华电容.pdf; 价格: 0.01191; 类别: 贴片电容0402; 品牌: 风华; 生命周期: 量产; 条码: EBF29060121
C77 C136 C137 C164 = CAP_NP: 规格: 贴片电容NC 预留; 类别: 贴片电容0402; 条码: EBF29060149
C81 C82 C200-C202 C206-C208 = CAP_NP: voltage: 25V; 规格: 贴片电容47uF 20% 25V X5R 1206; 规格编号: GRM31CR61E476ME44L; 规格书: 村田贴片电容.pdf; 价格: 1.12; 类别: 贴片电容1206; 品牌: 村田; 生命周期: 量产; 条码: EBF29060192
C90 C205 C213 C214 = CAP_NP: voltage: 50V; 规格: 贴片电容1nF 20% 50V X7R 0402; 规格编号: 0402B102M500NT; 规格书: 风华电容.pdf; 价格: 0.006195; 类别: 贴片电容0402; 品牌: 风华; 生命周期: 量产; 条码: EBF29060175
C140 = CAP_NP: voltage: 50V; 规格: 贴片电容10pF 5% 50V C0G 0402; 规格编号: 0402CG100J500NT; 规格书: 风华电容.pdf; 价格: 0.00453; 类别: 贴片电容0402; 品牌: 风华; 生命周期: 量产; 条码: EBF29060127
C162 C165 C181 C203 C209 = CAP_NP: voltage: 25V; 规格: 贴片电容22uF 20% 25V X5R 0805; 规格编号: 0805X226M250NT; 规格书: 风华电容.pdf; 价格: 0.285631; 类别: 贴片电容0805; 品牌: 风华; 生命周期: 量产; 条码: EBF29060173
CN1 = WIFI_ANT: 规格: RF同轴连接器（天线座）; 规格编号: KH-IPEX-K501-29; 规格书: 金航标-天线座.pdf; 价格: 0.247224; 类别: WiFi天线座; 品牌: 金航标; 生命周期: 量产; 条码: EBF430005
D14-D17 D25 D30 D47 D57 = DIODE_BI-DIR_TRIG: 备注: 通用; 规格: 防静电保护ESD二极管 反向工作电压5V 击穿电压7V 钳位电压10.5V 结电容Cj 0.3pF; 规格书: 千虹_D2315-5R0B.pdf; 类别: 贴片ESD; 品牌: 千虹; 生命周期: 量产; 条码: EBFCIS240517170922
J8 = PJ-393: 备注: RK3566广告机; 规格: PJ-393-7P_3.5MM四段式耳机插座 7pin 直插; 规格书: 成旭辉_PJ-393-7P直插耳机座.pdf; 类别: 耳机座; 品牌: 成旭辉; 生命周期: 量产; 条码: EBFCIS230522094626
J9 J22 = 1X2PIN: 规格: 直针PH2.0-2P 间距2.0MM 拔插式 接插件; 规格书: 博穆精密_PH2.0-A.pdf; 价格: 0.019031; 可替代料: EBF29040005; 类别: PH连接器; 品牌: 博穆精密; 生命周期: 量产; 条码: EBF29040005
L8 L9 L15-L17 = BEAD: 规格: 磁珠120Ω @100MHz 额定电流1A 直流电阻120mΩ; 规格编号: PZ1005U121-1R0TF; 规格书: 顺络-磁珠120Ω±25%100MHZ.pdf; 价格: 0.020259; 类别: 贴片磁珠0402; 品牌: 顺络; 生命周期: 量产; 条码: EBF29050044
L18-L21 = BEAD: 备注: RK3566广告机; 规格: 磁珠1K@100MHz额定电流600mA直流电阻350mΩ; 规格编号: BLM18HE102SN1D; 规格书: 村田_BLM18H_SN系列磁珠.pdf; 价格: 0.149038; 类别: 贴片磁珠0603; 品牌: 村田; 生命周期: 量产; 条码: EBFCIS230428095012
P1 = MIC_POM: 规格: 4*1.2mm咪头 双电容驻极体话筒 拾音器 工作电压1.5V-10V 灵敏度-62DB 低阻抗; 规格编号: GMI4015P-2C-62db; 规格书: 赢海_GMI4015P-2C-62db.pdf; 价格: 0.868384; 类别: 麦克风; 品牌: 赢海; 生命周期: 量产; 条码: EBFCIS221130183008
Q4 Q5 = MOSFET_N: 备注: 立创停售; 规格: N沟道MOS 导通电阻47mΩ 电流3.6A 4.5V 阈值电压(Vgs(th)@Id)1V 连续漏极电流2.9A; 规格书: WNM2016-3_TR.pdf; 类别: N-MOS; 品牌: 韦尔; 条码: EBF29280014
Q11 Q15 Q16 = MOSFET_P: 规格: P沟道MOS 导通电阻60mΩ 电流4.1A 3V可驱动; 规格书: 合科泰-AO3407.pdf; 价格: 0.199827; 类别: P-MOS; 品牌: 合科泰; 生命周期: 量产; 丝印: A7; 条码: EBF29280012
R81 R85 R88 R89 R92 R93 R138 R143 R166-R170 R173-R175 = RES: 规格: 贴片电阻0R 1% 1/16W 0402; 规格编号: RI0402L000FT; 规格书: 合科泰-RI系列电阻.pdf; 类别: 贴片电阻0402; 品牌: 合科泰; 生命周期: 量产; 条码: EBF29070049
R82 R97 R182 R183 R201-R204 = RES: 规格: 贴片电阻100R 1% 1/16W 0402; 规格编号: RI0402L1000FT; 规格书: 合科泰-RI系列电阻.pdf; 类别: 贴片电阻0402; 品牌: 合科泰; 生命周期: 量产; 条码: EBF29070053
R83 R86 R87 R172 = RES: 规格: 贴片电阻100K 1% 1/16W 0402; 规格编号: RI0402L1003FT; 规格书: 合科泰-RI系列电阻.pdf; 类别: 贴片电阻0402; 品牌: 合科泰; 生命周期: 量产; 条码: EBF29070054
R84 R160 R162 R163 R188-R190 R235-R238 = RES: 规格: 贴片电阻2.2K 1% 1/16W 0402; 规格编号: RI0402L2201FT; 规格书: 合科泰-RI系列电阻.pdf; 类别: 贴片电阻0402; 品牌: 合科泰; 生命周期: 量产; 条码: EBF29070051
R90 R94 R242 R243 = RES: 规格: 贴片电阻470R 1% 1/16W 0402; 规格编号: 0402WGF4700TCE; 规格书: 厚声-无铅厚膜电阻.pdf; 价格: 0.002728; 类别: 贴片电阻0402; 品牌: 厚声; 生命周期: 量产; 条码: EBF29070284
R95 = RES: 规格: 贴片电阻300K 1% 1/16W 0402; 规格编号: RI0402L3003FT; 规格书: 合科泰-RI系列电阻.pdf; 类别: 贴片电阻0402; 品牌: 合科泰; 生命周期: 量产; 条码: EBF29070220
R96 R98 R192 R223 R224 = RES: 规格: 贴片电阻20K 1% 1/16W 0402; 规格编号: 0402WGF2002TCE; 规格书: 厚声-无铅厚膜电阻.pdf; 价格: 0.002473; 类别: 贴片电阻0402; 品牌: 厚声; 生命周期: 量产; 条码: EBF29070223
R99 R101 R102 R155 R177 R193 R195 R200 R225 = RES: 规格: 贴片电阻1K 1% 1/16W 0402; 规格编号: RI0402L1001FT; 规格书: 合科泰-RI系列电阻.pdf; 类别: 贴片电阻0402; 品牌: 合科泰; 生命周期: 量产; 条码: EBF29070050
R191 R219 R221 = RES: 规格: 贴片电阻0R 1% 1/10W 0603; 规格编号: RI0603L0000FT; 规格书: 合科泰-RI系列电阻.pdf; 类别: 贴片电阻0603; 品牌: 合科泰; 生命周期: 量产; 条码: EBF29070063
R220 R222 = RES: 规格: 贴片电阻NC 预留; 类别: 贴片电阻0603; 条码: EBF29070088
U9 = ES8388: 规格: 音频接口芯片 模拟供电1.7V~3.6V 核心与IO供电1.5V~3.6V; 规格书: 顺芯_ES8388.pdf; 价格: 3.904; 类别: 音频芯片; 品牌: 顺芯; 条码: EBFCIS221116105415
U10 U38 = NS4110B: 备注: RK3566广告机; 规格: 单声道AB/D类音频功率放大器 工作电压:6V~14V 输出功率:18W@4Ω 超低EMI 支持差分输入; 规格书: 纳芯威_NS4110B音频功放.pdf; 类别: 音频芯片; 品牌: 纳芯威; 生命周期: 量产; 条码: EBFCIS230518164803
U22 = RTL8723: 规格: RTL8821 WiFi模块 接口类型：usb 工作电压：3.3V 传输速率：150M+433M 工作频率：2.4G+5.8G 无线标准：802.11AC/B/G/n 有效通信距离：100m; 价格: 17; 类别: WiFi模块; 品牌: 创凌; 生命周期: 量产; 条码: EBF29250002
J14-J18 = FPC-24P: 规格: FPC连接器 针脚数24 间距0.5mmm 下接 卧贴 翻盖式; 规格编号: AFC01-S24FCA-00; 规格书: 钜硕电子-FPC间距0.5mm.pdf; 价格: 0.368739; 可替代料: EBF29040059; 类别: FPC连接器; 品牌: 钜硕电子; 生命周期: 量产; 条码: EBF29040059
C135 = CAP: voltage: 6.3V; 规格: 贴片电容220uF 20% 6.3V 坦电容 CASE-B_3528; 规格编号: TLJB227M006R0500; 规格书: AVX_贴片坦电容.pdf; 价格: 1.28; 类别: 贴片坦电容; 品牌: AVX; 生命周期: 量产; 条码: EBF29060264
C167-C169 = CAP_NP: voltage: 50V; 规格: 贴片电容33pF 5% 50V 0402; 规格编号: 0402CG330J500NT; 规格书: 风华电容.pdf; 类别: 贴片电容0402; 品牌: 风华; 生命周期: 量产; 条码: EBF29060298
D32 D33 = DIODE_BI-DIR_TRIG: 规格: 用于 USB3.0、HDMI 0.5pF、5V、±15kV ESD 保护二极管; 规格书: KLXES15AAA1.pdf; 价格: 0.09719; 类别: 贴片ESD; 品牌: 永裕泰; 生命周期: 量产; 条码: EBF29140063
J19 = SIM-7-1: 规格: nano sim卡座; 规格编号: HYC63-SIM07-137; 规格书: 华宇创_NANOSIMPUSH1.37H带CDPIN带柱.pdf; 价格: 1.48; 可替代料: EBF29040054; 类别: SIM卡座连接器; 品牌: 华宇创; 生命周期: 量产; 条码: EBF29040054
J20 = MINI-PCIE: 备注: 鲁班猫1/3/4; 规格: MINI PCIE插座 引脚数：52P 高度6.8mm; 规格编号: PCIE-52P68H; 规格书: XUNPU(讯普)_52PMINIPCIE插座.pdf; 可替代料: EBF29040055; 类别: 金手指连接器; 品牌: 讯普; 生命周期: 量产; 条码: EBFCIS250409174317
L14 = IND: 规格: 贴片电感3.3uH ±20% 3A 直流电阻69mΩ; 规格编号: TMPC0402HP-3R3MG-Z02; 规格书: 台庆-功率电感.pdf; 价格: 1.5992; 类别: 贴片电感0402; 品牌: 台庆; 生命周期: 量产; 条码: EBF29050040
R171 = RES: 规格: 贴片电阻15K 1% 1/16W 0402; 规格编号: RI0402L1502FT; 规格书: 合科泰-RI系列电阻.pdf; 类别: 贴片电阻0402; 品牌: 合科泰; 生命周期: 量产; 条码: EBF29070222
R176 = RES: 规格: 贴片电阻30K 1% 1/16W 0402; 规格编号: RI0402L3002FT; 规格书: 合科泰-RI系列电阻.pdf; 类别: 贴片电阻0402; 品牌: 合科泰; 生命周期: 量产; 条码: EBF29070048
R184 R185 = RES: 规格: 贴片电阻2.2R 1% 1/16W 0402; 规格编号: 0402WGF220KTCE; 规格书: 厚声-无铅厚膜电阻.pdf; 价格: 0.003072; 类别: 贴片电阻0402; 品牌: 厚声; 生命周期: 量产; 条码: EBF29070280
SS7 SS8 = SPACER: 规格: SMT贴片螺母M2 台阶高度1.4MM 台阶外径：2.8MM 螺柱长度：4MM; 规格编号: SMTWE2040CTJ; 规格书: 雄和远景_SMTWE2040CTJ.pdf; 类别: 贴片螺母; 品牌: 雄和远景; 生命周期: 量产; 条码: EBFCIS221028103338
U26 = TP6327GS6: 备注: RK3566金手指与BTB底板替换物料; 规格: DC-DC电源芯片 可输出电流 3A 开关工作频率 600kHz 输出类型 ADJ 输入电压范围：4V-18V; 规格书: 安森德_ASP9135ZC-R.pdf; 类别: 电源管理-DCDC; 品牌: 安森德; 生命周期: 量产; 条码: EBFCIS240710113940
U27 = NUP5120-D: 规格: 防静电保护ESD二极管 击穿电压6.2V 反向关断电压5V 封装SOT-523; 规格书: 安森美_NUP5120X6T1G.pdf; 价格: 0.39; 类别: 贴片ESD; 品牌: 安森美; 生命周期: 量产; 条码: EBF29140034
J23 = 1X6PIN: 规格: 直针PH2.0-6P 间距2.0MM 拔插式 接插件; 规格书: 博穆精密_PH2.0-A.pdf; 价格: 0.0228; 可替代料: EBF29020026; 类别: PH连接器; 品牌: 博穆精密; 生命周期: 量产; 条码: EBF29020026
Q17 = NPN: 规格: 贴片三极管SS8050 集电极电流1.5A 额定功率300mW NPN; 规格书: 江苏长电-SS8050Y1.pdf; 价格: 0.086744; 类别: 贴片三极管SOT-23; 品牌: 江苏长电; 生命周期: 量产; 丝印: Y1; 条码: EBF29090001
R196 R197 = RES: 规格: 贴片电阻3.4K 1% 1/16W 0402; 规格编号: RI0402L3401FT; 规格书: 合科泰-RI系列电阻.pdf; 类别: 贴片电阻0402; 品牌: 合科泰; 生命周期: 量产; 条码: EBF29070186
U31 U32 = LPW5209AB5F: 规格: 集成电源开关 导通电阻：80mΩ 最大可设置保护电流：2.1A 输入电压：2.5V~6V 静态电流：30uA 其他功能：软启动、短路保护、热保护; 规格书: 微源半导体_LPW5209AB5F.pdf; 价格: 0.468063; 类别: 功率开关; 品牌: 微源半导体; 生命周期: 量产; 条码: EBF29280015
D37-D40 = DIODE_BI-DIR_TRIG: 规格: 防静电保护ESD二极管 箝位电压26V 击穿电压5.8V 反向关断电压3.3V; 规格编号: PESD3V3L1BA 115; 规格书: 安世-PESD3V3L1BA-115.pdf; 价格: 0.31497; 类别: 贴片ESD; 品牌: 安世; 生命周期: 量产; 丝印: AB; 条码: EBF29140003
DN1 DN2 = TVS_Arr_ComA: 规格: 防静电保护ESD二极管 箝位电压12V -7V 击穿电压13.3V -7.5V; 规格书: 时科_SM712.pdf; 价格: 0.273512; 类别: 贴片ESD; 品牌: 时科; 生命周期: 量产; 条码: EBFCIS221015085507
J24 = CON6: 规格: 绿色插拔式接线端子 间距3.81mm 90度弯针 6PIN; 规格编号: WJ15EDGRC-3.81-6P; 规格书: 康奈克斯电气-绿色端子弯针插座.pdf; 价格: 0.301748; 类别: 绿色插拔式接线端子; 品牌: 康奈克斯电气; 生命周期: 量产; 条码: EBF29040013
J25 J26 = 1X4PIN: 规格: 直针PH2.0-4P 间距2.0MM 拔插式 接插件; 规格书: 博穆精密-PH2.0.pdf; 价格: 0.017; 可替代料: EBF29020025; 类别: PH连接器; 品牌: 博穆精密; 生命周期: 量产; 条码: EBF29020025
J27 J28 = 2X3PIN: 规格: 蓝色直插双排排针 总PIN数6 间距2.54mm; 规格编号: HDR2X3-2R54-TM-VM-BLUE; 规格书: 州日_双排针_直插_2P54.pdf; 类别: 2.54mm直插双排排针; 品牌: 州日; 生命周期: 量产; 条码: EBF29020030
J29 J31 = CON4: 规格: 插拔式接线端子 间距3.81mm 90度弯针 4PIN; 规格书: 康奈克斯电气-绿色端子弯针插座.pdf; 价格: 0.198381; 类别: 绿色插拔式接线端子; 品牌: 康奈克斯电气; 生命周期: 量产; 条码: EBF29040009
R205 R206 R211 R216 = RES: 规格: 贴片电阻120R 1% 1/16W 0402; 规格编号: 0402WGF1200TCE; 规格书: 厚声-无铅厚膜电阻.pdf; 价格: 0.002198; 类别: 贴片电阻0402; 品牌: 厚声; 生命周期: 量产; 条码: EBF29070275
U33 = MAX3232CSE: 备注: 鲁班猫; 规格: RS232芯片 收发器 驱动器/接收器数：2/2 协议类别RS232 电源电压3.0V~5.5V 数据速率96kbps; 规格书: 芯力特_SIT3232E-V1.17-cn.pdf; 类别: RS232芯片; 品牌: 芯力特; 生命周期: 量产; 条码: EBFCIS231207155139
U34 U35 = TJA1057GT3_8P: 备注: 替代TJA1042T/3/1J; 规格: CAN芯片 收发器 驱动器/接收器数：1/1 协议类别CAN总线 电源电压4.5V~5.5V 数据速率5Mbps; 规格书: 芯力特_SIT1042.pdf; 价格: 1.98; 类别: CAN芯片; 品牌: 芯力特; 生命周期: 量产; 条码: EBFCIS230524153230
U36 U37 = SIT3088E-8P: 备注: 鲁班猫; 规格: RS-485/RS-422芯片 收发器 允许256个器件连接总线 协议类别RS-485 电源电压3.0V~5.5V 数据速率14Mbps; 规格书: 芯力特_SIT3088E-V1.8_cn.pdf; 类别: RS485/RS422芯片; 品牌: 芯力特; 生命周期: 量产; 条码: EBFCIS231207153322

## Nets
3V3_OUT: C183.1 C185.1 J23.5 U31.1(OUT)
3V3_WLAN: C141.1 C142.1 Q11.3(DRAIN) U22.8(VCC3V3)
5V_OUT: C186.1 C187.1 J23.3 U32.1(OUT)
12V: C162.1 C163.1 C180.1 Q15.3(DRAIN) R192.1 R219.1 R221.1 U26.3(VIN)
12V_OUT: C181.1 C182.1 J23.1 Q16.3(DRAIN)
GND: C33.2 C34.2 C35.2 C36.2 C37.2 C38.2 C39.2 C40.2 C41.2 C42.2 C43.2 C44.2 C45.2 C46.2 C47.2 C48.2 C49.2 C50.2 C51.2 C52.2 C53.2 C54.2 C55.2 C56.2 C57.2 C58.2 C59.2 C60.2 C61.2 C62.2 C63.2 C64.2 C65.2 C66.2 C67.2 C68.2 C69.2 C70.2 C72.2 C73.2 C77.2 C78.2 C79.2 C80.2 C83.2 C84.2 C85.2 C87.1 C88.2 C90.2 C135.2 C136.2 C137.2 C141.2 C142.2 C144.2 C147.2 C149.2 C150.2 C151.2 C152.2 C153.2 C154.2 C155.2 C156.2 C157.2 C158.2 C159.2 C160.2 C162.2 C163.2 C165.2 C166.2 C167.2 C168.2 C169.2 C172.2 C173.2 C174.2 C175.2 C181.2 C182.2 C183.2 C184.2 C185.2 C186.2 C187.2 C188.2 C189.2 C190.2 C191.2 C194.2 C195.2 C196.2 C197.2 C198.2 C199.2 C200.2 C201.2 C202.2 C203.2 C204.2 C205.2 C206.2 C207.2 C208.2 C209.2 C210.2 C212.1 C213.2 C214.2 C215.2 CN1.2 CN1.3 D14.1 D15.1 D16.1 D17.1 D25.2 D30.2 D32.2 D33.2 D37.1 D38.1 D39.1 D40.1 D47.2 D57.2 DN1.3(A) DN2.3(A) J14.4 J14.18 J14.21 J14.23 J14.24 J14.25(SH1) J14.26(SH2) J15.4 J15.18 J15.21 J15.23 J15.24 J15.25(SH1) J15.26(SH2) J16.4 J16.18 J16.21 J16.23 J16.24 J16.25(SH1) J16.26(SH2) J17.4 J17.18 J17.21 J17.23 J17.24 J17.25(SH1) J17.26(SH2) J18.4 J18.18 J18.21 J18.23 J18.24 J18.25(SH1) J18.26(SH2) J19.5(GND) J19.8(SH1) J19.9(SH2) J19.10(SH3) J19.11(SH4) J20.4(GND9) J20.9(GND1) J20.15(GND2) J20.18(GND10) J20.21(GND3) J20.26(GND11) J20.27(GND4) J20.29(GND5) J20.34(GND12) J20.35(GND6) J20.37(GND7) J20.40(GND13) J20.43(GND8) J20.50(GND14) J20.53 J20.54 J23.2 J23.4 J23.6 J24.2 J24.5 J25.4 J26.4 Q17.2(EMITTER) R38.2 R43.2 R44.2 R45.2 R50.2 R51.2 R54.2 R55.2 R56.2 R62.2 R65.2 R66.2 R69.2 R74.2 R75.2 R78.2 R79.2 R80.2 R85.1 R86.2 R90.2 R92.2 R94.2 R100.2 R101.2 R176.2 R178.2 R194.2 R196.2 R197.2 R212.2 R214.2 R217.2 R218.2 R226.2 R242.2 R243.2 SS7.1(NC) SS8.1(NC) U7.41(GND) U8.41(GND) U9.4(DGND) U9.13(HPGND) U9.18(AGND) U9.29(EPAD) U10.7(GND) U10.9(EPAD) U22.1(GND) U22.5(GND) U26.1(GND) U27.2 U31.2(GND) U32.2(GND) U33.15(GND) U34.2(GND) U34.8(S) U35.2(GND) U35.8(S) U36.5(GND) U37.5(GND) U38.7(GND) U38.9(EPAD) Y2.2(GND1) Y2.4(GND2) Y3.2(GND1) Y3.4(GND2) ; also on sheet 8 9 10
VCC_1V8_S3: R158.1 R159.1 ; also on sheet 9
VDD_3V3: C33.1 C34.1 C35.1 C49.1 C50.1 C51.1 C143.1 C189.1 C196.1 L5.1 L7.1 L8.1 L9.1 L15.2 L16.1 L17.1 Q11.2(SOURCE) R33.1 R34.1 R35.1 R46.1 R47.1 R48.1 R53.1 R57.1 R58.1 R59.1 R70.1 R71.1 R72.1 R77.1 R82.2 R87.1 R91.1 R97.2 R148.1 R160.1 R162.1 R163.1 R188.1 R189.1 R190.1 R235.1 R236.1 R237.1 R238.1 U7.28(DVDD_RG) U7.29(DVDD33) U8.28(DVDD_RG) U8.29(DVDD33) U31.5(IN) U34.5(VIO) U35.5(VIO) ; also on sheet 8 9 10
VDD_5V: C151.1 C152.1 C153.1 C154.1 C155.1 C156.1 C157.1 C158.1 C159.1 C160.1 C190.1 C197.1 R166.1 R167.1 R168.1 R169.1 R170.1 R220.1 R222.1 U32.5(IN) U34.3(VCC) U35.3(VCC) ; also on sheet 8 10
CAM0_PWDN: J14.15
CAM0_RSTN: J14.22
CAM1_PWDN: J15.15
CAM1_RSTN: J15.22
CAM2_PWDN: J16.15
CAM2_RSTN: J16.22
CAM3_PWDN: J18.15
CAM3_RSTN: J18.22
CAM4_PWDN: J17.15
CAM4_RSTN: J17.22
CAN0_H: D57.1 J29.1 R205.1 U34.7(CANH)
CAN0_L: D47.1 J29.2 R205.2 U34.6(CANL)
CAN0_RX_M2: U34.4(RXD)
CAN0_TX_M2: U34.1(TXD)
CAN1_H: D30.1 J29.3 R206.1 U35.7(CANH)
CAN1_L: D25.1 J29.4 R206.2 U35.6(CANL)
CAN1_RX_M3: U35.4(RXD)
CAN1_TX_M3: U35.1(TXD)
EARPHONE_CTL: R95.2
ETH0_MCLK_M0: R49.1
ETH0_MDC_M0: R48.2 U7.13(MDC)
ETH0_MDIO_M0: R47.2 U7.14(MDIO)
ETH0_RSTn: D59.1
ETH0_RXCLK_M0: R41.1 R44.1
ETH0_RXCTL_M0: R42.1 R45.1
ETH0_RXD0_M0: R33.2 R37.1
ETH0_RXD1_M0: R34.2 R36.1
ETH0_RXD2_M0: R39.1 R43.1
ETH0_RXD3_M0: R35.2 R40.1
ETH0_TXCLK_M0: U7.20(TXC)
ETH0_TXCTL_M0: U7.19(TXCTL)
ETH0_TXD0_M0: U7.18(TXD0)
ETH0_TXD1_M0: U7.17(TXD1)
ETH0_TXD2_M0: U7.16(TXD2)
ETH0_TXD3_M0: U7.15(TXD3)
ETH1_MCLK_M0: R73.1
ETH1_MDC_M0: R72.2 U8.13(MDC)
ETH1_MDIO_M0: R71.2 U8.14(MDIO)
ETH1_RSTn: D60.1
ETH1_RXCLK_M0: R59.2 R67.1
ETH1_RXCTL_M0: R68.1 R69.1
ETH1_RXD0_M0: R57.2 R60.1
ETH1_RXD1_M0: R58.2 R61.1
ETH1_RXD2_M0: R63.1 R65.1
ETH1_RXD3_M0: R64.1 R66.1
ETH1_TXCLK_M0: U8.20(TXC)
ETH1_TXCTL_M0: U8.19(TXCTL)
ETH1_TXD0_M0: U8.18(TXD0)
ETH1_TXD1_M0: U8.17(TXD1)
ETH1_TXD2_M0: U8.16(TXD2)
ETH1_TXD3_M0: U8.15(TXD3)
HP_BUTTON_DET: C77.1 R83.2 R86.1
HP_PLUG_IN_DET: R88.2
I2C3_SCL_M0: J14.6 R162.2 U9.28(CCLK) ; also on sheet 9
I2C3_SDA_M0: J14.5 R160.2 U9.27(CDATA) ; also on sheet 9
I2C4_SCL_M2: J15.6 R188.2
I2C4_SDA_M2: J15.5 R163.2
I2C5_SCL_M3: J16.6 R190.2
I2C5_SDA_M3: J16.5 R189.2
I2C7_SCL_M1: J18.6 R236.2
I2C7_SDA_M1: J18.5 R235.2
I2C8_SCL_M2: J17.6 R238.2
I2C8_SDA_M2: J17.5 R237.2
LOUT1: C81.2 U9.12(LOUT1)
LOUT2: C86.1 U9.15(LOUT2)
MIC1N: C74.2 R85.2
MIC1P: C71.2 R81.2
MIC2N: C76.2 C89.2 P1.2(GND) R101.1
MIC2P: C75.2 C89.1 P1.1(Out) R99.2
MINIPCIE_3V3: C135.1 C164.2 C165.1 C166.1 C172.1 C173.1 C174.1 C175.1 J20.2(VBAT1) J20.24(VBAT5) J20.39(VBAT2) J20.41(VBAT3) J20.52(VBAT4) L14.2 R172.2 R179.1
MINIPCIE_nWDISABLE: R182.2
MINIPCIE_PWR_EN: R177.1
MIPI_DPHY_CSI0_RX_CLKN: J14.10
MIPI_DPHY_CSI0_RX_CLKP: J14.9
MIPI_DPHY_CSI0_RX_D0N: J14.12
MIPI_DPHY_CSI0_RX_D0P: J14.11
MIPI_DPHY_CSI0_RX_D1N: J14.8
MIPI_DPHY_CSI0_RX_D1P: J14.7
MIPI_DPHY_CSI0_RX_D2N: J14.17
MIPI_DPHY_CSI0_RX_D2P: J14.16
MIPI_DPHY_CSI0_RX_D3N: J14.20
MIPI_DPHY_CSI0_RX_D3P: J14.19
MIPI_DPHY_CSI1_RX_CLKN: J15.10
MIPI_DPHY_CSI1_RX_CLKP: J15.9
MIPI_DPHY_CSI1_RX_D0N: J15.12
MIPI_DPHY_CSI1_RX_D0P: J15.11
MIPI_DPHY_CSI1_RX_D1N: J15.8
MIPI_DPHY_CSI1_RX_D1P: J15.7
MIPI_DPHY_CSI2_RX_CLKN: J16.10
MIPI_DPHY_CSI2_RX_CLKP: J16.9
MIPI_DPHY_CSI2_RX_D0N: J16.12
MIPI_DPHY_CSI2_RX_D0P: J16.11
MIPI_DPHY_CSI2_RX_D1N: J16.8
MIPI_DPHY_CSI2_RX_D1P: J16.7
MIPI_DPHY_CSI3_RX_CLKN: J18.10
MIPI_DPHY_CSI3_RX_CLKP: J18.9
MIPI_DPHY_CSI3_RX_D0N: J18.12
MIPI_DPHY_CSI3_RX_D0P: J18.11
MIPI_DPHY_CSI3_RX_D1N: J18.8
MIPI_DPHY_CSI3_RX_D1P: J18.7
MIPI_DPHY_CSI4_RX_CLKN: J17.10
MIPI_DPHY_CSI4_RX_CLKP: J17.9
MIPI_DPHY_CSI4_RX_D0N: J17.12
MIPI_DPHY_CSI4_RX_D0P: J17.11
MIPI_DPHY_CSI4_RX_D1N: J17.8
MIPI_DPHY_CSI4_RX_D1P: J17.7
PCIE0_CLKREQN_M0: R181.1
PCIE0_PERSTN: R183.2
PCIE0_REFCLKN: J20.11(VDD-EXT)
PCIE0_REFCLKP: J20.13(RESERVED)
PCIE0_RXN: J20.23(UART-RXD)
PCIE0_RXP: J20.25(UART-RTS)
PCIE0_TXN: C170.1
PCIE0_TXP: C171.1
PCIE0_WAKEN_M0: R180.1
PE_TXN: C170.2 J20.31(UART-TXD)
PE_TXP: C171.2 J20.33(PERST2)
PWR_3V3_EN: R195.1
PWR_5V_EN: R200.1
PWR_12V_EN: R193.1
RMII0_AVDD33: C46.1 C47.1 C48.1 L5.2 R52.2 U7.11(AVDD33_1) U7.40(AVDD33)
RMII0_LED1: C150.1 J6.14(YELA) R56.1 U7.33(LED1)
RMII0_LED2: C149.1 J6.11(GRLA) R54.1 U7.34(LED2)
RMII0_MDIN0: J6.3(TD1-) U7.2(MDIN0)
RMII0_MDIN1: J6.7(RD1-) U7.5(MDIN1)
RMII0_MDIN2: J6.6(TD2-) U7.7(MDIN2)
RMII0_MDIN3: J6.9(RD2-) U7.10(MDIN3)
RMII0_MDIP0: J6.2(TD1+) U7.1(MDIP0)
RMII0_MDIP1: J6.4(RD1+) U7.4(MDIP1)
RMII0_MDIP2: J6.5(TD2+) U7.6(MDIP2)
RMII0_MDIP3: J6.8(RD2+) U7.9(MDIP3)
RMII0_VDD10: C36.1 C37.1 C38.1 C39.1 C40.1 L4.2 U7.3(AVDD10_2) U7.8(AVDD10_1) U7.21(DVDD10) U7.38(AVDD10)
RMII1_AVDD33: C62.1 C63.1 C64.1 L7.2 R76.2 U8.11(AVDD33_1) U8.40(AVDD33)
RMII1_LED1: C147.1 J7.14(YELA) R80.1 U8.33(LED1)
RMII1_LED2: C144.1 J7.11(GRLA) R79.1 U8.34(LED2)
RMII1_MDIN0: J7.3(TD1-) U8.2(MDIN0)
RMII1_MDIN1: J7.7(RD1-) U8.5(MDIN1)
RMII1_MDIN2: J7.6(TD2-) U8.7(MDIN2)
RMII1_MDIN3: J7.9(RD2-) U8.10(MDIN3)
RMII1_MDIP0: J7.2(TD1+) U8.1(MDIP0)
RMII1_MDIP1: J7.4(RD1+) U8.4(MDIP1)
RMII1_MDIP2: J7.5(TD2+) U8.6(MDIP2)
RMII1_MDIP3: J7.8(RD2+) U8.9(MDIP3)
RMII1_VDD10: C52.1 C53.1 C54.1 C55.1 C56.1 L6.2 U8.3(AVDD10_2) U8.8(AVDD10_1) U8.21(DVDD10) U8.38(AVDD10)
ROUT1: C82.2 U9.11(ROUT1)
ROUT2: C211.1 U9.14(ROUT2)
RS232_R1IN: J24.4 U33.13(R1IN)
RS232_R1OUT: J27.1 U33.12(R1OUT)
RS232_R2IN: J24.1 U33.8(R2IN)
RS232_R2OUT: J28.1 U33.9(R2OUT)
RS232_T1IN: J27.2 U33.11(T1IN)
RS232_T1OUT: J24.6 U33.14(T1OUT)
RS232_T2IN: J28.2 U33.10(T2IN)
RS232_T2OUT: J24.3 U33.7(T2OUT)
RS485_1_3V3: C198.1 D41.2 L16.2 U36.8(VCC)
RS485_1_A: DN1.2(C2) J31.2 R211.2 R213.1 U36.6(A)
RS485_1_B: DN1.1(C1) J31.1 R211.1 R214.1 U36.7(B)
RS485_1_DIR: R212.1 U36.2(~{RE}) U36.3(DE)
RS485_2_3V3: C199.1 D42.2 L17.2 U37.8(VCC)
RS485_2_A: DN2.2(C2) J31.4 R215.1 R216.2 U37.6(A)
RS485_2_B: DN2.1(C1) J31.3 R216.1 R218.1 U37.7(B)
RS485_2_DIR: R217.1 U37.2(~{RE}) U37.3(DE)
SAI1_LRCK_M0: U9.7(LRCK)
SAI1_MCLK_M0: U9.1(MCLK)
SAI1_SCLK_M0: U9.5(SCLK)
SAI1_SDI0_M0: U9.8(ASDOUT)
SAI1_SDO2_M0: U9.6(DSDIN)
SIM_CLK0: J20.12(USIM-CLK) R174.1
SIM_DATA0: J20.10(USIM-DATA) R175.1
SIM_RST0: J20.14(USIM-RST) R173.1
SIM_VDD: J19.1(VCC) J20.8(USIM-VDD) R171.1 U27.1
SPK_CTRL: R102.1 R225.1
SPK_LN: C205.1 J9.1 L18.2
SPK_LP: C90.1 J9.2 L19.2
SPK_RN: C214.1 J22.1 L20.2
SPK_RP: C213.1 J22.2 L21.2
U8_RX: J25.3 J27.5
U8_TX: J25.2 J27.6
U10_RX: J26.3 J28.5
U10_TX: J26.2 J28.6
UART3_RX_M1: U36.1(RXD)
UART3_TX_M1: U36.4(TXD)
UART5_RX_M0: U37.1(RXD)
UART5_TX_M0: U37.4(TXD)
UART8_RX: D38.2 J27.3 R203.2
UART8_RX_M2: R203.1
UART8_TX: D37.2 J27.4 R204.2
UART8_TX_M2: R204.1
UART10_RX: D40.2 J28.3 R201.2
UART10_RX_M1: R201.1
UART10_TX: D39.2 J28.4 R202.2
UART10_TX_M1: R202.1
USB_HUB_DM5: D33.1 R184.2 ; also on sheet 10
USB_HUB_DM6: R143.1 ; also on sheet 10
USB_HUB_DP5: D32.1 R185.2 ; also on sheet 10
USB_HUB_DP6: R138.1 ; also on sheet 10
WIFI_PWR_EN: R155.1
N16970771: R39.2 U7.23(RXD2)
N16970773: R36.2 U7.24(RXD1)
N16970775: R37.2 U7.25(RXD0)
N16970777: R42.2 U7.26(RXCTL)
N16970779: R41.2 U7.27(RXC)
N16970781: R40.2 U7.22(RXD3)
N16970797: R49.2 U7.35(CLKOUT)
N16970858: C42.1 U7.36(XTAL_IN) Y2.3
N16970862: C41.1 U7.37(XTAL_OUT) Y2.1
N16970890: C45.1 D59.2 R53.2 R158.2 U7.12(PHYRSTB)
N16971097: R38.1 U7.39(RSET)
N16971189: L4.1 U7.30(REG_OUT)
N16971238: C43.1 J6.1(CT)
N16971259: C44.1 J6.10(CHS) J6.15(SH) J6.16(SH1) R55.1
N16971318: J6.12(GRLC) R50.1
N16971320: J6.13(YELC) R51.1
N16971466: R52.1 U7.32(LED0)
N16971541: R46.2 U7.31(INTB)
N16976499: R68.2 U8.26(RXCTL)
N16976501: R60.2 U8.25(RXD0)
N16976503: R61.2 U8.24(RXD1)
N16976505: R63.2 U8.23(RXD2)
N16976507: R64.2 U8.22(RXD3)
N16976509: R67.2 U8.27(RXC)
N16976515: R73.2 U8.35(CLKOUT)
N16976541: C57.1 U8.37(XTAL_OUT) Y3.1
N16976545: C58.1 U8.36(XTAL_IN) Y3.3
N16976569: C61.1 D60.2 R77.2 R159.2 U8.12(PHYRSTB)
N16976627: R62.1 U8.39(RSET)
N16976649: L6.1 U8.30(REG_OUT)
N16976697: R76.1 U8.32(LED0)
N16976807: C59.1 J7.1(CT)
N16976809: C60.1 J7.10(CHS) J7.15(SH) J7.16(SH1) R78.1
N16976831: J7.13(YELC) R75.1
N16976833: J7.12(GRLC) R74.1
N16976861: R70.2 U8.31(INTB)
N17018699: J15.1 J15.2 J15.3 R167.2
N17022868: J16.1 J16.2 J16.3 R168.2
N17023671: J18.1 J18.2 J18.3 R170.2
N17024139: J17.1 J17.2 J17.3 R169.2
N17026345: J14.1 J14.2 J14.3 R166.2
N17036087: C169.1 J19.2(RST) R173.2 U27.6
N17036090: C168.1 J19.3(CLK) R174.2 U27.4
N17036093: C167.1 J19.7(I/O) R171.2 R175.2 U27.5
N17043477: C161.2 L14.1 U26.2(SW)
N17043505: C161.1 U26.6(BOOT)
N17043507: C164.1 R172.1 R176.1 U26.4(FB)
N17043614: R177.2 R178.1 U26.5(EN)
N17043933: J20.1(MIC-P) R179.2 R180.2
N17044212: J20.7(SPK-N) R181.2
N17046085: J20.38(USB-D+) R185.1
N17046088: J20.36(USB-D-) R184.1
N17046548: J20.20(W-DISABLE) R182.1
N17046561: J20.22(PERST1) R183.1
N17063858: C66.1 C67.1 C68.1 C69.1 L8.2 U9.16(HPVDD) U9.17(AVDD)
N17063899: C72.1 C73.1 L9.2 U9.2(DVDD) U9.3(PVDD)
N17064255: C71.1 U9.24(LIN1)
N17064258: C74.1 U9.23(RIN1)
N17064495: C75.1 U9.22(LIN2)
N17064497: C76.1 U9.21(RIN2)
N17064707: C78.1 U9.20(VMID)
N17064710: C79.1 U9.19(ADCVREF)
N17064713: C80.1 U9.10(VREF)
N17064960: R91.2 U9.26(CE)
N17065329: C85.1 R97.1 R99.1
N17072089: C65.1 D14.2 J8.1 R81.1 R83.1 R84.2
N17072509: C70.1 R82.1 R84.1
N17073944: J8.2 R92.1
N17074279: C83.1 D15.2 J8.6 R87.2 R88.1
N17074336: D17.2 J8.3 Q5.2(SOURCE) R243.1
N17074726: D16.2 J8.4 Q4.2(SOURCE) R242.1
N17074747: Q4.3(DRAIN) R89.1 R90.1
N17075125: C81.1 R89.2
N17075408: Q5.3(DRAIN) R93.1 R94.1
N17075443: C82.1 R93.2
N17075521: C84.1 Q4.1(GATE) Q5.1(GATE) R95.1
N17240897: C180.2 Q15.1(GATE) Q16.1(GATE) Q17.3(COLLECTOR) R192.2
N17241015: Q15.2(SOURCE) R191.1
N17241092: Q16.2(SOURCE) R191.2
N17241660: Q17.1(BASE) R193.2 R194.1
N17241919: C184.1 R195.2 U31.4(EN)
N17241951: R196.1 U31.3(ISET)
N17242291: C188.1 R200.2 U32.4(EN)
N17242323: R197.1 U32.3(ISET)
N17272255: C191.1 L15.1 U33.16(VCC)
N17272410: C192.1 U33.3(C1-)
N17272413: C192.2 U33.1(C1+)
N17272453: C193.2 U33.4(C2+)
N17272456: C193.1 U33.5(C2-)
N17272490: C194.1 U33.6(V-)
N17272493: C195.1 U33.2(V+)
N17284003: D41.1 R213.2
N17284390: D42.1 R215.2
N17313600: C200.1 C201.1 C202.1 C203.1 C204.1 R219.2 R220.2 U38.6(VDD)
N17313897: R96.2 U38.4(INN)
N17313900: R98.2 U38.3(INP)
N17314015: C87.2 R98.1
N17314022: C86.2 R96.1
N17314158: R100.1 R102.2 U38.1(CTRL)
N17314600: C88.1 U38.2(BYPASS)
N17314610: L18.1 U38.5(VON)
N17314613: L19.1 U38.8(VOP)
N17315365: C206.1 C207.1 C208.1 C209.1 C210.1 R221.2 R222.2 U10.6(VDD)
N17315397: R224.2 U10.3(INP)
N17315399: R223.2 U10.4(INN)
N17315425: C212.2 R224.1
N17315432: C211.2 R223.1
N17315446: R225.2 R226.1 U10.1(CTRL)
N17315502: C215.1 U10.2(BYPASS)
N17315506: L21.1 U10.8(VOP)
N17315508: L20.1 U10.5(VON)
N17366542: C136.1 C140.1 U22.2(RF0)
N17366552: C137.1 C140.2 CN1.1
N17367118: R138.2 U22.6(D+)
N17367190: R143.2 U22.7(D-)
N17367932: C143.2 Q11.1(GATE) R148.2 R155.2

Not connected (* = marked no-connect by the designer): J8 7* 8*; J14 13* 14*; J15 13* 14* 16* 17* 19* 20*; J16 13* 14* 16* 17* 19* 20*; J17 13* 14* 16* 17* 19* 20*; J18 13* 14* 16* 17* 19* 20*; J19 4(CD)* 6(VPP)*; J20 3(MIC-N)* 5(SPK-P)* 6(NC1)* 16(RESERVED6)* 17(RESERVED5)* 19(WAKEUP-IN)* 28(UART-CTS)* 30(UART-DCD)* 32(WAKEUP-OUT)* 42(LED-WWAN)* 44(USIM-PRESENCE)* 45(RESERVED1)* 46(UART-DTR)* 47(RESERVED2)* 48(NC2)* 49(RESERVED3)* 51(RESERVED4)*; J25 1*; J26 1*; U9 9(NC1)* 25(NC2)*; U22 3(RF1)* 4(XIN)* 9(SUSPEND)* 10(WO_WLAN)* 11(BT_PCM_CLK)* 12(BT_PCM_SYNC)* 13(BT_PCM_OUT)* 14(BT_PCM_IN)*; U27 3*

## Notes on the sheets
sheet 1
- ETH0
- TXC/RXC:delay 2ns
  PHY Address:001
- PHYAD[0]
- PHYAD[1]
- PHYAD[2]
- 电流走向
- 配置 I/O VDD
  LED[001]=3.3V
  LED[01X]=2.5V
  LED[10X]=1.8V
  LED[11X]=1.5V
- R53
- JL2101-N040C
- 10K
- RTL8211F
- NC
- R158
- NC
- 10K
sheet 2
- KEY
- TXC/RXC:delay 2ns
  PHY Address:010
- PHYAD[0]
- PHYAD[1]
- PHYAD[2]
- 电流走向
- 配置 I/O VDD
  LED[001]=3.3V
  LED[01X]=2.5V
  LED[10X]=1.8V
  LED[11X]=1.5V
- JL2101-N040C
- RTL8211F
- R77
- 10K
- NC
- R159
- NC
- 10K
sheet 3
- MIPI CSI0 PORT
- MIPI CSI1 PORT
- MIPI CSI2 PORT
- GPIO1_D2
- GPIO2_B0
- GPIO2_B4
- GPIO1_D3
- GPIO2_B3
- GPIO2_B5
- MIPI CSI3 PORT
- MIPI CSI4 PORT
- GPIO3_C6
- GPIO1_D4
- GPIO3_C7
- GPIO3_C0
sheet 4
- MINI PCIE PWR
- SIM CARD
- GPIO0_D3
- MINI PCIE
- 贴片螺母
- GPIO0_D2
- GPIO4_C7
- GPIO2_B1
sheet 5
- Power OutPut SW
- Power Output
- OCP：3.3V 2A
  OCP：5V 2A
- GPIO0_A0
- GPIO0_C7
- GPIO0_C6
sheet 6
- CODEC
- EarPhone
- MIC
- GPIO4_B0
- 7bit i2c address:0x11
- GPIO4_B2
- SPK功放
- WIFI
- GPIO1_B7
- GPIO3_A4
- Z0=50Ω
sheet 7
- RS485
- RS232
- GPIO0_C3
- GPIO0_C5
- CAN
